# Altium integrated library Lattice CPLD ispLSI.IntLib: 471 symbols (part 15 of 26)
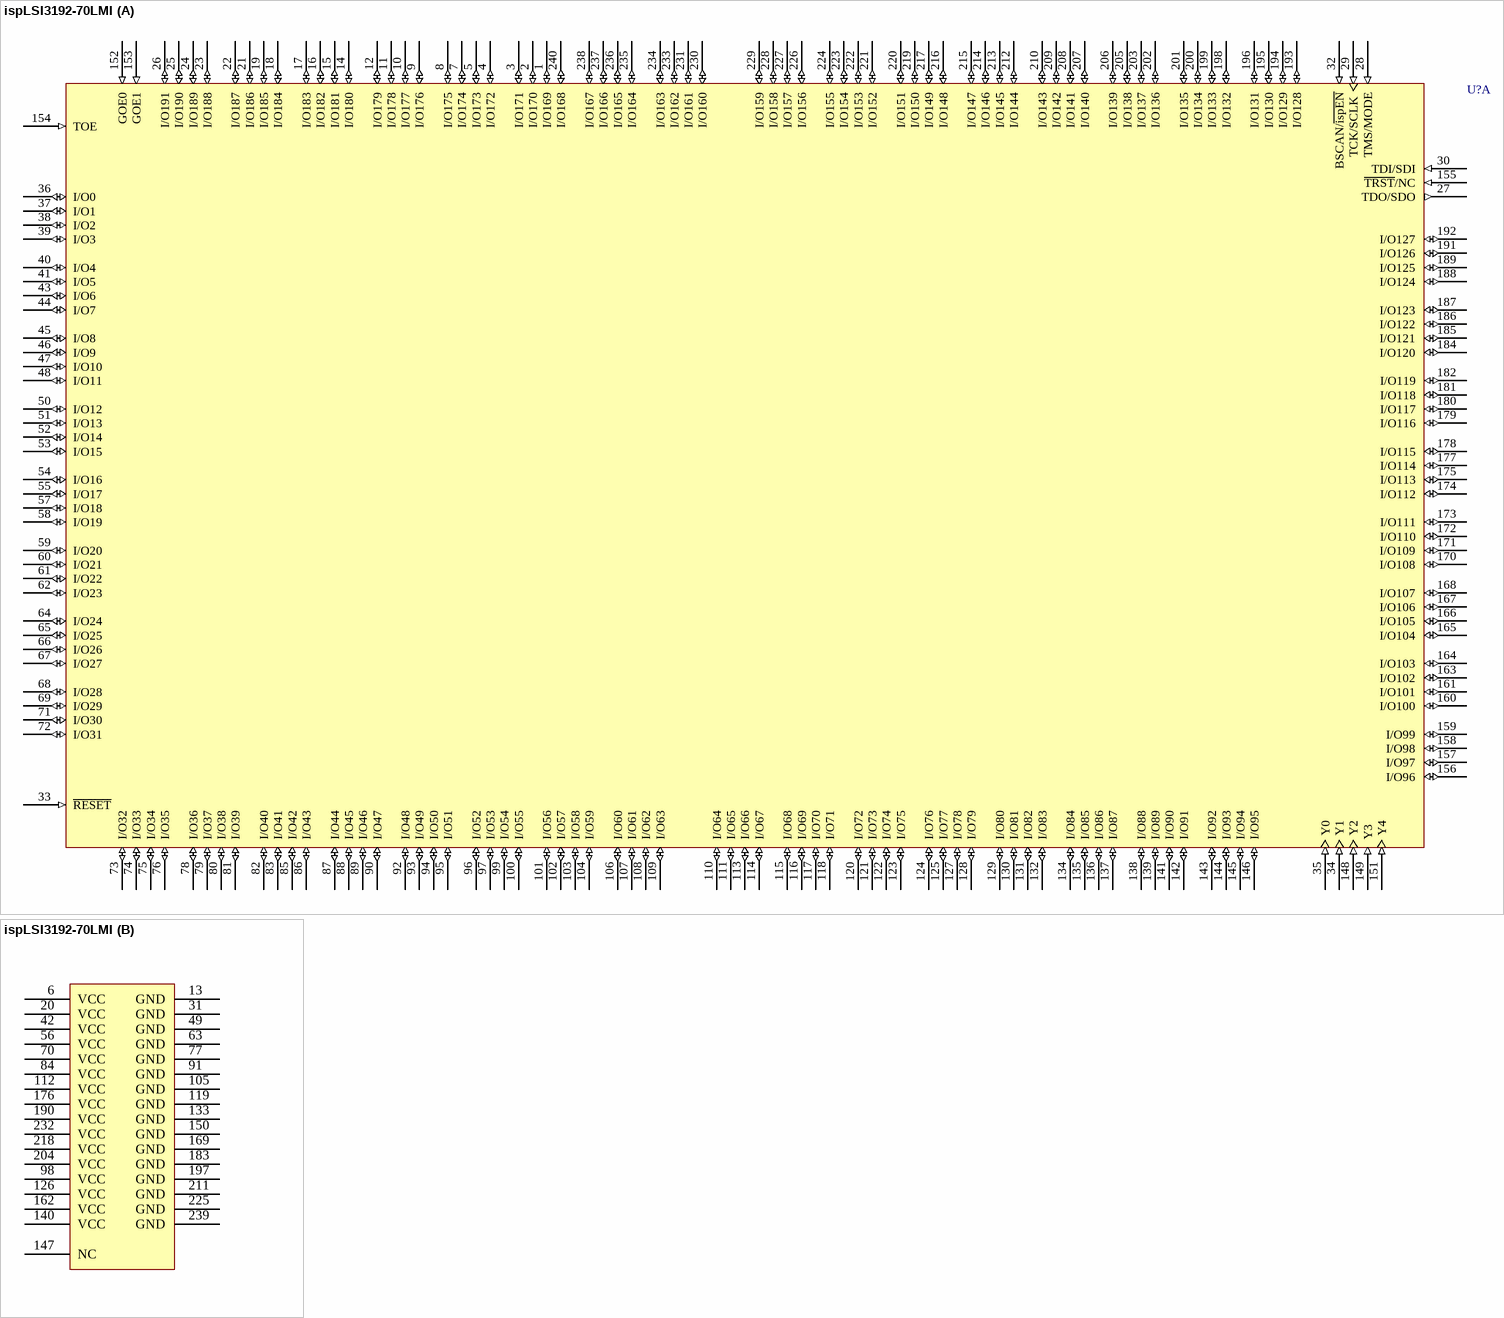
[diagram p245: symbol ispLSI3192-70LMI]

## ispLSI3192-70LMI
designator U?
High-Density Programmable Logic; Note: Pins 27, 28, 29, 30, 32 and 155 have dual function capability.
footprint MQFP240_N (Shrink QFP, 240-Leads, Body 31.7x31.7mm, Pitch 0.5mm, IPC Medium Density)
footprint MQFP240_L (Shrink QFP, 240-Leads, Body 31.7x31.7mm, Pitch 0.5mm, IPC High Density)
footprint MQFP240_M (Shrink QFP, 240-Leads, Body 31.7x31.7mm, Pitch 0.5mm, IPC Low Density)
3D model 3192-MQFP240 (240-Pin Shrink Quad Flat Pack 0.5 mm Pitch)
part A pins: 1 I/O169 (io), 2 I/O170 (io), 3 I/O171 (io), 4 I/O172 (io), 5 I/O173 (io), 7 I/O174 (io), 8 I/O175 (io), 9 I/O176 (io), 10 I/O177 (io), 11 I/O178 (io), 12 I/O179 (io), 14 I/O180 (io), 15 I/O181 (io), 16 I/O182 (io), 17 I/O183 (io), 18 I/O184 (io), 19 I/O185 (io), 21 I/O186 (io), 22 I/O187 (io), 23 I/O188 (io), 24 I/O189 (io), 25 I/O190 (io), 26 I/O191 (io), 27 TDO/SDO (out), 28 TMS/MODE (in), 29 TCK/SCLK (in), 30 TDI/SDI (in), 32 BSCAN/~{ispEN} (in), 33 ~{RESET} (in), 34 Y1 (in), 35 Y0 (in), 36 I/O0 (io), 37 I/O1 (io), 38 I/O2 (io), 39 I/O3 (io), 40 I/O4 (io), 41 I/O5 (io), 43 I/O6 (io), 44 I/O7 (io), 45 I/O8 (io), 46 I/O9 (io), 47 I/O10 (io), 48 I/O11 (io), 50 I/O12 (io), 51 I/O13 (io), 52 I/O14 (io), 53 I/O15 (io), 54 I/O16 (io), 55 I/O17 (io), 57 I/O18 (io), 58 I/O19 (io), 59 I/O20 (io), 60 I/O21 (io), 61 I/O22 (io), 62 I/O23 (io), 64 I/O24 (io), 65 I/O25 (io), 66 I/O26 (io), 67 I/O27 (io), 68 I/O28 (io), 69 I/O29 (io), 71 I/O30 (io), 72 I/O31 (io), 73 I/O32 (io), 74 I/O33 (io), 75 I/O34 (io), 76 I/O35 (io), 78 I/O36 (io), 79 I/O37 (io), 80 I/O38 (io), 81 I/O39 (io), 82 I/O40 (io), 83 I/O41 (io), 85 I/O42 (io), 86 I/O43 (io), 87 I/O44 (io), 88 I/O45 (io), 89 I/O46 (io), 90 I/O47 (io), 92 I/O48 (io), 93 I/O49 (io), 94 I/O50 (io), 95 I/O51 (io), 96 I/O52 (io), 97 I/O53 (io), 99 I/O54 (io), 100 I/O55 (io), 101 I/O56 (io), 102 I/O57 (io), 103 I/O58 (io), 104 I/O59 (io), 106 I/O60 (io), 107 I/O61 (io), 108 I/O62 (io), 109 I/O63 (io), 110 I/O64 (io), 111 I/O65 (io), 113 I/O66 (io), 114 I/O67 (io), 115 I/O68 (io), 116 I/O69 (io), 117 I/O70 (io), 118 I/O71 (io), 120 I/O72 (io), 121 I/O73 (io), 122 I/O74 (io), 123 I/O75 (io), 124 I/O76 (io), 125 I/O77 (io), 127 I/O78 (io), 128 I/O79 (io), 129 I/O80 (io), 130 I/O81 (io), 131 I/O82 (io), 132 I/O83 (io), 134 I/O84 (io), 135 I/O85 (io), 136 I/O86 (io), 137 I/O87 (io), 138 I/O88 (io), 139 I/O89 (io), 141 I/O90 (io), 142 I/O91 (io), 143 I/O92 (io), 144 I/O93 (io), 145 I/O94 (io), 146 I/O95 (io), 148 Y2 (in), 149 Y3 (in), 151 Y4 (in), 152 GOE0 (in), 153 GOE1 (in), 154 TOE (in), 155 ~{TRST}/NC (in), 156 I/O96 (io), 157 I/O97 (io), 158 I/O98 (io), 159 I/O99 (io), 160 I/O100 (io), 161 I/O101 (io), 163 I/O102 (io), 164 I/O103 (io), 165 I/O104 (io), 166 I/O105 (io), 167 I/O106 (io), 168 I/O107 (io), 170 I/O108 (io), 171 I/O109 (io), 172 I/O110 (io), 173 I/O111 (io), 174 I/O112 (io), 175 I/O113 (io), 177 I/O114 (io), 178 I/O115 (io), 179 I/O116 (io), 180 I/O117 (io), 181 I/O118 (io), 182 I/O119 (io), 184 I/O120 (io), 185 I/O121 (io), 186 I/O122 (io), 187 I/O123 (io), 188 I/O124 (io), 189 I/O125 (io), 191 I/O126 (io), 192 I/O127 (io), 193 I/O128 (io), 194 I/O129 (io), 195 I/O130 (io), 196 I/O131 (io), 198 I/O132 (io), 199 I/O133 (io), 200 I/O134 (io), 201 I/O135 (io), 202 I/O136 (io), 203 I/O137 (io), 205 I/O138 (io), 206 I/O139 (io), 207 I/O140 (io), 208 I/O141 (io), 209 I/O142 (io), 210 I/O143 (io), 212 I/O144 (io), 213 I/O145 (io), 214 I/O146 (io), 215 I/O147 (io), 216 I/O148 (io), 217 I/O149 (io), 219 I/O150 (io), 220 I/O151 (io), 221 I/O152 (io), 222 I/O153 (io), 223 I/O154 (io), 224 I/O155 (io), 226 I/O156 (io), 227 I/O157 (io), 228 I/O158 (io), 229 I/O159 (io), 230 I/O160 (io), 231 I/O161 (io), 233 I/O162 (io), 234 I/O163 (io), 235 I/O164 (io), 236 I/O165 (io), 237 I/O166 (io), 238 I/O167 (io), 240 I/O168 (io)
part B pins: 6 VCC (power), 13 GND (power), 20 VCC (power), 31 GND (power), 42 VCC (power), 49 GND (power), 56 VCC (power), 63 GND (power), 70 VCC (power), 77 GND (power), 84 VCC (power), 91 GND (power), 98 VCC (power), 105 GND (power), 112 VCC (power), 119 GND (power), 126 VCC (power), 133 GND (power), 140 VCC (power), 147 NC, 150 GND (power), 162 VCC (power), 169 GND (power), 176 VCC (power), 183 GND (power), 190 VCC (power), 197 GND (power), 204 VCC (power), 211 GND (power), 218 VCC (power), 225 GND (power), 232 VCC (power), 239 GND (power)

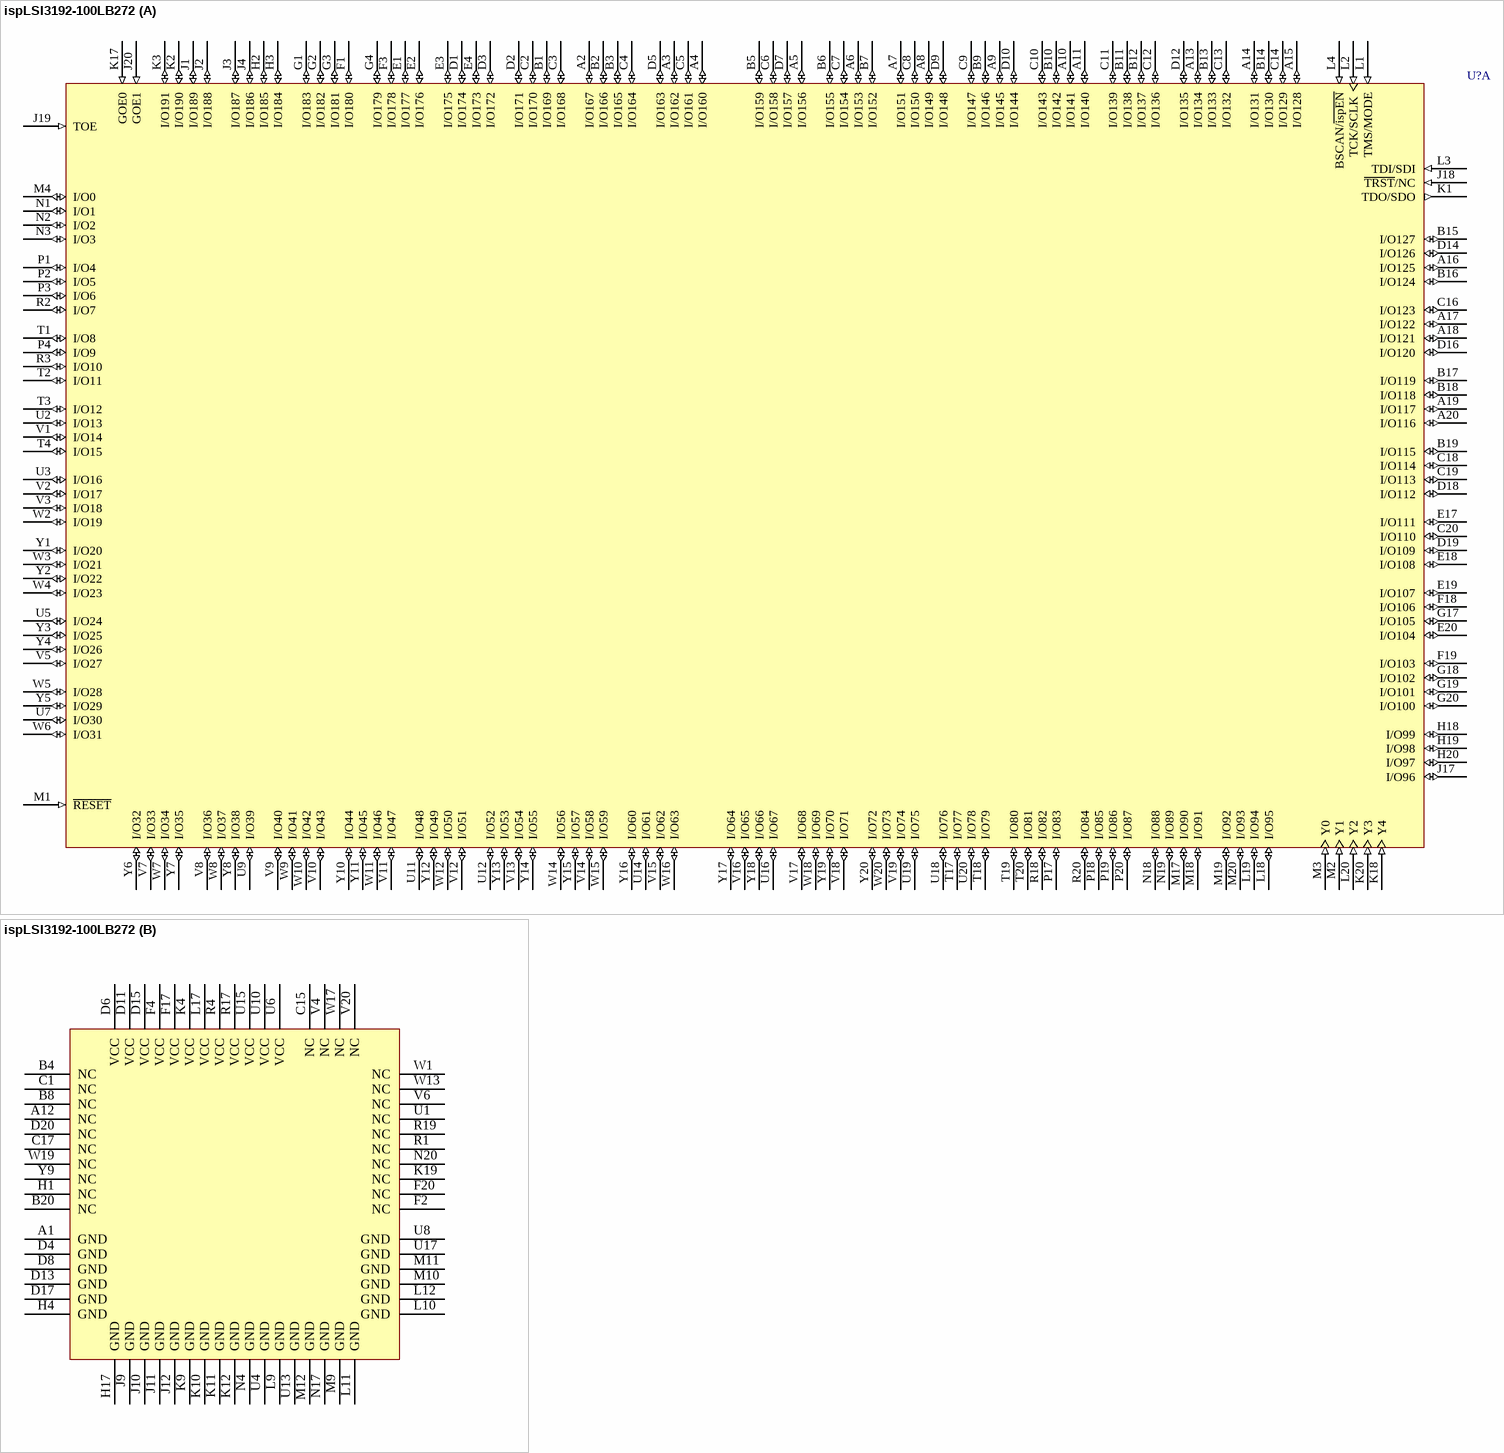
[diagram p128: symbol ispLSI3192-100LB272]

## ispLSI3192-100LB272
designator U?
High-Density Programmable Logic; Note: Pins J18, K1, L1, L2, L3 and L4 have dual function capability.
footprint BGA272 (BGA, 272-Leads, Body 27x27mm, Pitch 1.27mm)
3D model 3192-BGA272 (272-Ball Ball Grid Array (BGA272))
part A pins: A2 I/O167 (io), A3 I/O162 (io), A4 I/O160 (io), A5 I/O156 (io), A6 I/O153 (io), A7 I/O151 (io), A8 I/O149 (io), A9 I/O145 (io), A10 I/O141 (io), A11 I/O140 (io), A13 I/O134 (io), A14 I/O131 (io), A15 I/O128 (io), A16 I/O125 (io), A17 I/O122 (io), A18 I/O121 (io), A19 I/O117 (io), A20 I/O116 (io), B1 I/O169 (io), B2 I/O166 (io), B3 I/O165 (io), B5 I/O159 (io), B6 I/O155 (io), B7 I/O152 (io), B9 I/O146 (io), B10 I/O142 (io), B11 I/O138 (io), B12 I/O137 (io), B13 I/O133 (io), B14 I/O130 (io), B15 I/O127 (io), B16 I/O124 (io), B17 I/O119 (io), B18 I/O118 (io), B19 I/O115 (io), C2 I/O170 (io), C3 I/O168 (io), C4 I/O164 (io), C5 I/O161 (io), C6 I/O158 (io), C7 I/O154 (io), C8 I/O150 (io), C9 I/O147 (io), C10 I/O143 (io), C11 I/O139 (io), C12 I/O136 (io), C13 I/O132 (io), C14 I/O129 (io), C16 I/O123 (io), C18 I/O114 (io), C19 I/O113 (io), C20 I/O110 (io), D1 I/O174 (io), D2 I/O171 (io), D3 I/O172 (io), D5 I/O163 (io), D7 I/O157 (io), D9 I/O148 (io), D10 I/O144 (io), D12 I/O135 (io), D14 I/O126 (io), D16 I/O120 (io), D18 I/O112 (io), D19 I/O109 (io), E1 I/O177 (io), E2 I/O176 (io), E3 I/O175 (io), E4 I/O173 (io), E17 I/O111 (io), E18 I/O108 (io), E19 I/O107 (io), E20 I/O104 (io), F1 I/O180 (io), F3 I/O178 (io), F18 I/O106 (io), F19 I/O103 (io), G1 I/O183 (io), G2 I/O182 (io), G3 I/O181 (io), G4 I/O179 (io), G17 I/O105 (io), G18 I/O102 (io), G19 I/O101 (io), G20 I/O100 (io), H2 I/O185 (io), H3 I/O184 (io), H18 I/O99 (io), H19 I/O98 (io), H20 I/O97 (io), J1 I/O189 (io), J2 I/O188 (io), J3 I/O187 (io), J4 I/O186 (io), J17 I/O96 (io), J18 ~{TRST}/NC (in), J19 TOE (in), J20 GOE1 (in), K1 TDO/SDO (out), K2 I/O190 (io), K3 I/O191 (io), K17 GOE0 (in), K18 Y4 (in), K20 Y3 (in), L1 TMS/MODE (in), L2 TCK/SCLK (in), L3 TDI/SDI (in), L4 BSCAN/~{ispEN} (in), L18 I/O95 (io), L19 I/O94 (io), L20 Y2 (in), M1 ~{RESET} (in), M2 Y1 (in), M3 Y0 (in), M4 I/O0 (io), M17 I/O90 (io), M18 I/O91 (io), M19 I/O92 (io), M20 I/O93 (io), N1 I/O1 (io), N2 I/O2 (io), N3 I/O3 (io), N18 I/O88 (io), N19 I/O89 (io), P1 I/O4 (io), P2 I/O5 (io), P3 I/O6 (io), P4 I/O9 (io), P17 I/O83 (io), P18 I/O85 (io), P19 I/O86 (io), P20 I/O87 (io), R2 I/O7 (io), R3 I/O10 (io), R18 I/O82 (io), R20 I/O84 (io), T1 I/O8 (io), T2 I/O11 (io), T3 I/O12 (io), T4 I/O15 (io), T17 I/O77 (io), T18 I/O79 (io), T19 I/O80 (io), T20 I/O81 (io), U2 I/O13 (io), U3 I/O16 (io), U5 I/O24 (io), U7 I/O30 (io), U9 I/O39 (io), U11 I/O48 (io), U12 I/O52 (io), U14 I/O61 (io), U16 I/O67 (io), U18 I/O76 (io), U19 I/O75 (io), U20 I/O78 (io), V1 I/O14 (io), V2 I/O17 (io), V3 I/O18 (io), V5 I/O27 (io), V7 I/O33 (io), V8 I/O36 (io), V9 I/O40 (io), V10 I/O43 (io), V11 I/O47 (io), V12 I/O51 (io), V13 I/O54 (io), V14 I/O58 (io), V15 I/O62 (io), V16 I/O65 (io), V17 I/O68 (io), V18 I/O71 (io), V19 I/O74 (io), W2 I/O19 (io), W3 I/O21 (io), W4 I/O23 (io), W5 I/O28 (io), W6 I/O31 (io), W7 I/O34 (io), W8 I/O37 (io), W9 I/O41 (io), W10 I/O42 (io), W11 I/O46 (io), W12 I/O50 (io), W14 I/O56 (io), W15 I/O59 (io), W16 I/O63 (io), W18 I/O69 (io), W20 I/O73 (io), Y1 I/O20 (io), Y2 I/O22 (io), Y3 I/O25 (io), Y4 I/O26 (io), Y5 I/O29 (io), Y6 I/O32 (io), Y7 I/O35 (io), Y8 I/O38 (io), Y10 I/O44 (io), Y11 I/O45 (io), Y12 I/O49 (io), Y13 I/O53 (io), Y14 I/O55 (io), Y15 I/O57 (io), Y16 I/O60 (io), Y17 I/O64 (io), Y18 I/O66 (io), Y19 I/O70 (io), Y20 I/O72 (io)
part B pins: A1 GND (power), A12 NC, B4 NC, B8 NC, B20 NC, C1 NC, C15 NC, C17 NC, D4 GND (power), D6 VCC (power), D8 GND (power), D11 VCC (power), D13 GND (power), D15 VCC (power), D17 GND (power), D20 NC, F2 NC, F4 VCC (power), F17 VCC (power), F20 NC, H1 NC, H4 GND (power), H17 GND (power), J9 GND (power), J10 GND (power), J11 GND (power), J12 GND (power), K4 VCC (power), K9 GND (power), K10 GND (power), K11 GND (power), K12 GND (power), K19 NC, L9 GND (power), L10 GND (power), L11 GND (power), L12 GND (power), L17 VCC (power), M9 GND (power), M10 GND (power), M11 GND (power), M12 GND (power), N4 GND (power), N17 GND (power), N20 NC, R1 NC, R4 VCC (power), R17 VCC (power), R19 NC, U1 NC, U4 GND (power), U6 VCC (power), U8 GND (power), U10 VCC (power), U13 GND (power), U15 VCC (power), U17 GND (power), V4 NC, V6 NC, V20 NC, W1 NC, W13 NC, W17 NC, W19 NC, Y9 NC

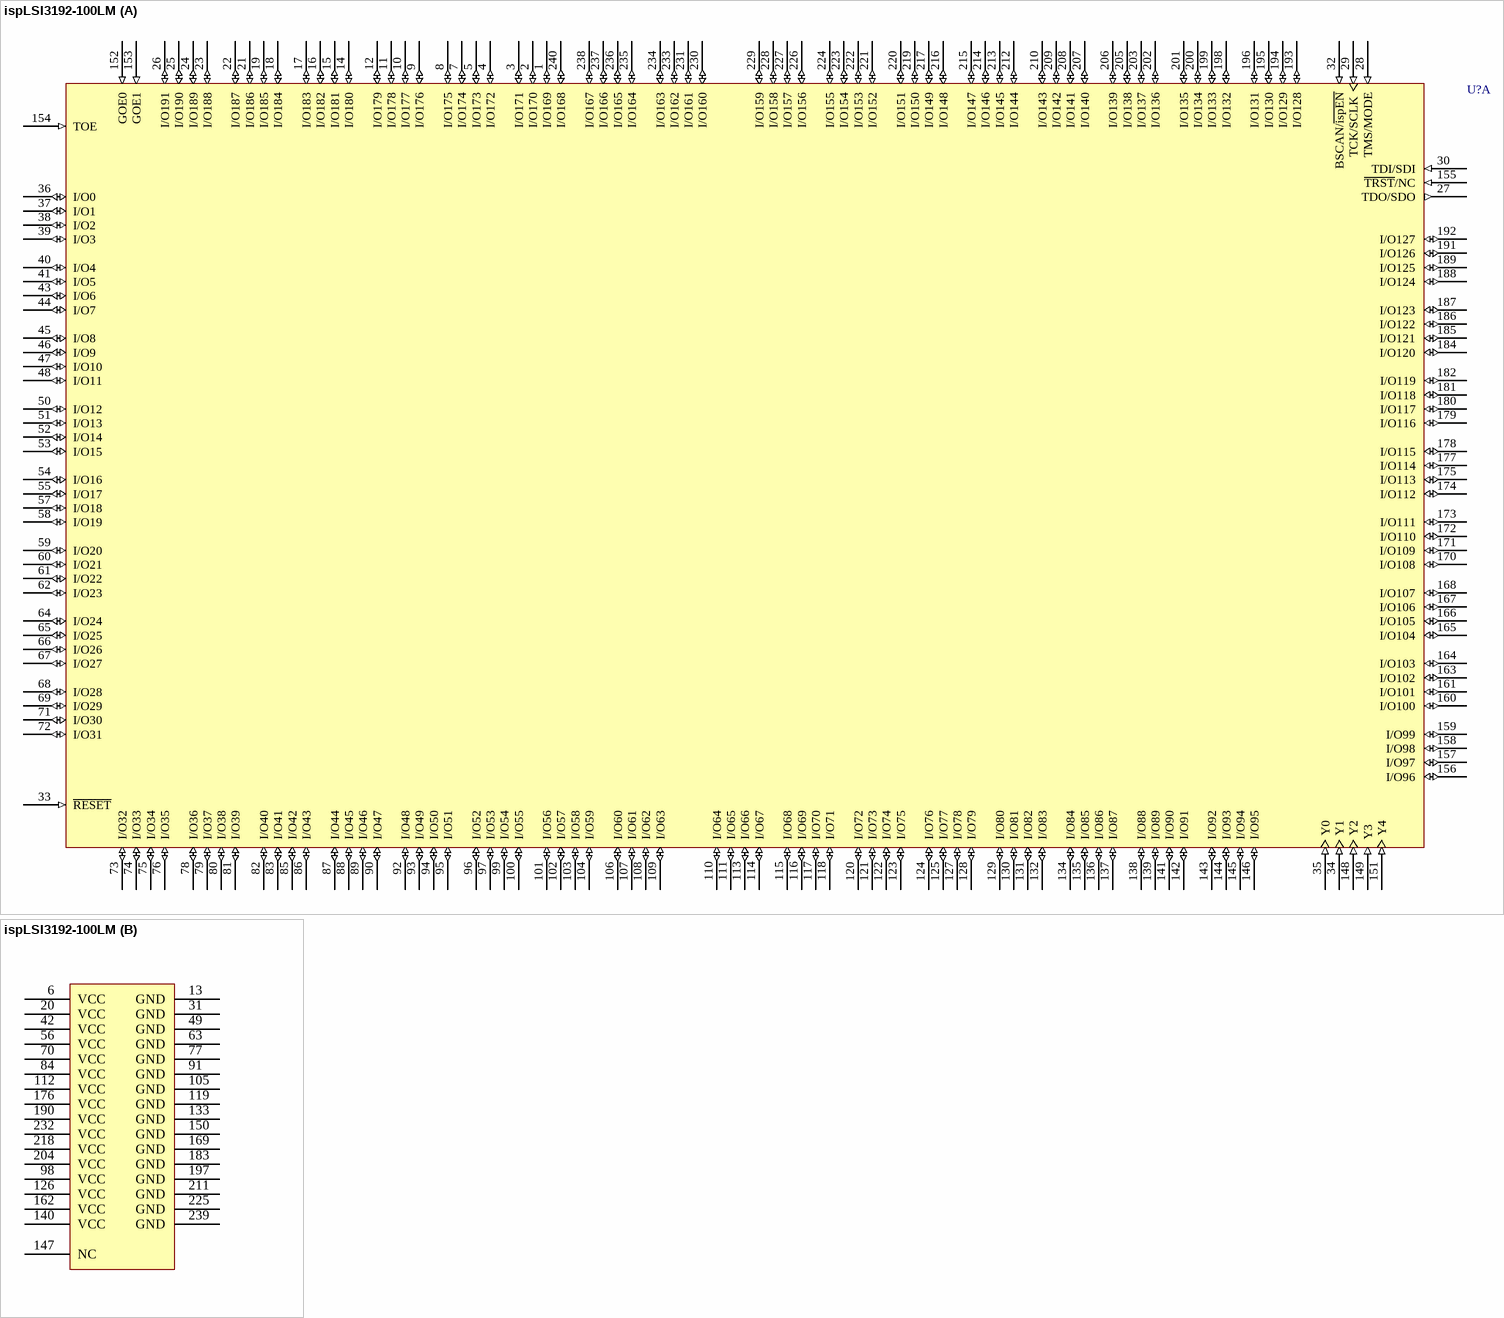
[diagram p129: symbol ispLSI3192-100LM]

## ispLSI3192-100LM
designator U?
High-Density Programmable Logic; Note: Pins 27, 28, 29, 30, 32 and 155 have dual function capability.
footprint MQFP240_N (Shrink QFP, 240-Leads, Body 31.7x31.7mm, Pitch 0.5mm, IPC Medium Density)
footprint MQFP240_L (Shrink QFP, 240-Leads, Body 31.7x31.7mm, Pitch 0.5mm, IPC High Density)
footprint MQFP240_M (Shrink QFP, 240-Leads, Body 31.7x31.7mm, Pitch 0.5mm, IPC Low Density)
3D model 3192-MQFP240 (240-Pin Shrink Quad Flat Pack 0.5 mm Pitch)
part A pins: 1 I/O169 (io), 2 I/O170 (io), 3 I/O171 (io), 4 I/O172 (io), 5 I/O173 (io), 7 I/O174 (io), 8 I/O175 (io), 9 I/O176 (io), 10 I/O177 (io), 11 I/O178 (io), 12 I/O179 (io), 14 I/O180 (io), 15 I/O181 (io), 16 I/O182 (io), 17 I/O183 (io), 18 I/O184 (io), 19 I/O185 (io), 21 I/O186 (io), 22 I/O187 (io), 23 I/O188 (io), 24 I/O189 (io), 25 I/O190 (io), 26 I/O191 (io), 27 TDO/SDO (out), 28 TMS/MODE (in), 29 TCK/SCLK (in), 30 TDI/SDI (in), 32 BSCAN/~{ispEN} (in), 33 ~{RESET} (in), 34 Y1 (in), 35 Y0 (in), 36 I/O0 (io), 37 I/O1 (io), 38 I/O2 (io), 39 I/O3 (io), 40 I/O4 (io), 41 I/O5 (io), 43 I/O6 (io), 44 I/O7 (io), 45 I/O8 (io), 46 I/O9 (io), 47 I/O10 (io), 48 I/O11 (io), 50 I/O12 (io), 51 I/O13 (io), 52 I/O14 (io), 53 I/O15 (io), 54 I/O16 (io), 55 I/O17 (io), 57 I/O18 (io), 58 I/O19 (io), 59 I/O20 (io), 60 I/O21 (io), 61 I/O22 (io), 62 I/O23 (io), 64 I/O24 (io), 65 I/O25 (io), 66 I/O26 (io), 67 I/O27 (io), 68 I/O28 (io), 69 I/O29 (io), 71 I/O30 (io), 72 I/O31 (io), 73 I/O32 (io), 74 I/O33 (io), 75 I/O34 (io), 76 I/O35 (io), 78 I/O36 (io), 79 I/O37 (io), 80 I/O38 (io), 81 I/O39 (io), 82 I/O40 (io), 83 I/O41 (io), 85 I/O42 (io), 86 I/O43 (io), 87 I/O44 (io), 88 I/O45 (io), 89 I/O46 (io), 90 I/O47 (io), 92 I/O48 (io), 93 I/O49 (io), 94 I/O50 (io), 95 I/O51 (io), 96 I/O52 (io), 97 I/O53 (io), 99 I/O54 (io), 100 I/O55 (io), 101 I/O56 (io), 102 I/O57 (io), 103 I/O58 (io), 104 I/O59 (io), 106 I/O60 (io), 107 I/O61 (io), 108 I/O62 (io), 109 I/O63 (io), 110 I/O64 (io), 111 I/O65 (io), 113 I/O66 (io), 114 I/O67 (io), 115 I/O68 (io), 116 I/O69 (io), 117 I/O70 (io), 118 I/O71 (io), 120 I/O72 (io), 121 I/O73 (io), 122 I/O74 (io), 123 I/O75 (io), 124 I/O76 (io), 125 I/O77 (io), 127 I/O78 (io), 128 I/O79 (io), 129 I/O80 (io), 130 I/O81 (io), 131 I/O82 (io), 132 I/O83 (io), 134 I/O84 (io), 135 I/O85 (io), 136 I/O86 (io), 137 I/O87 (io), 138 I/O88 (io), 139 I/O89 (io), 141 I/O90 (io), 142 I/O91 (io), 143 I/O92 (io), 144 I/O93 (io), 145 I/O94 (io), 146 I/O95 (io), 148 Y2 (in), 149 Y3 (in), 151 Y4 (in), 152 GOE0 (in), 153 GOE1 (in), 154 TOE (in), 155 ~{TRST}/NC (in), 156 I/O96 (io), 157 I/O97 (io), 158 I/O98 (io), 159 I/O99 (io), 160 I/O100 (io), 161 I/O101 (io), 163 I/O102 (io), 164 I/O103 (io), 165 I/O104 (io), 166 I/O105 (io), 167 I/O106 (io), 168 I/O107 (io), 170 I/O108 (io), 171 I/O109 (io), 172 I/O110 (io), 173 I/O111 (io), 174 I/O112 (io), 175 I/O113 (io), 177 I/O114 (io), 178 I/O115 (io), 179 I/O116 (io), 180 I/O117 (io), 181 I/O118 (io), 182 I/O119 (io), 184 I/O120 (io), 185 I/O121 (io), 186 I/O122 (io), 187 I/O123 (io), 188 I/O124 (io), 189 I/O125 (io), 191 I/O126 (io), 192 I/O127 (io), 193 I/O128 (io), 194 I/O129 (io), 195 I/O130 (io), 196 I/O131 (io), 198 I/O132 (io), 199 I/O133 (io), 200 I/O134 (io), 201 I/O135 (io), 202 I/O136 (io), 203 I/O137 (io), 205 I/O138 (io), 206 I/O139 (io), 207 I/O140 (io), 208 I/O141 (io), 209 I/O142 (io), 210 I/O143 (io), 212 I/O144 (io), 213 I/O145 (io), 214 I/O146 (io), 215 I/O147 (io), 216 I/O148 (io), 217 I/O149 (io), 219 I/O150 (io), 220 I/O151 (io), 221 I/O152 (io), 222 I/O153 (io), 223 I/O154 (io), 224 I/O155 (io), 226 I/O156 (io), 227 I/O157 (io), 228 I/O158 (io), 229 I/O159 (io), 230 I/O160 (io), 231 I/O161 (io), 233 I/O162 (io), 234 I/O163 (io), 235 I/O164 (io), 236 I/O165 (io), 237 I/O166 (io), 238 I/O167 (io), 240 I/O168 (io)
part B pins: 6 VCC (power), 13 GND (power), 20 VCC (power), 31 GND (power), 42 VCC (power), 49 GND (power), 56 VCC (power), 63 GND (power), 70 VCC (power), 77 GND (power), 84 VCC (power), 91 GND (power), 98 VCC (power), 105 GND (power), 112 VCC (power), 119 GND (power), 126 VCC (power), 133 GND (power), 140 VCC (power), 147 NC, 150 GND (power), 162 VCC (power), 169 GND (power), 176 VCC (power), 183 GND (power), 190 VCC (power), 197 GND (power), 204 VCC (power), 211 GND (power), 218 VCC (power), 225 GND (power), 232 VCC (power), 239 GND (power)

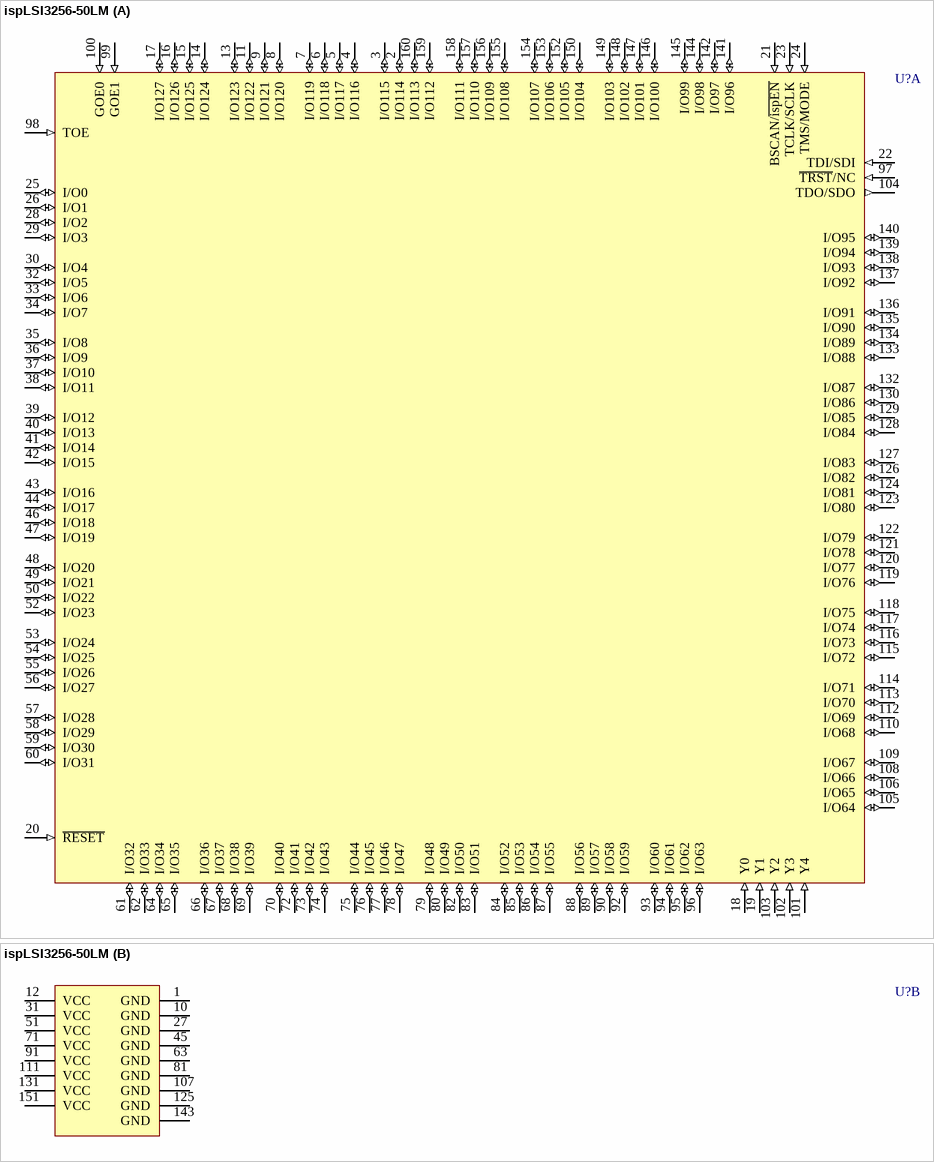
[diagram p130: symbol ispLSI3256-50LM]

## ispLSI3256-50LM
designator U?
High-Density Programmable Logic; Note: Pins 21, 22, 23, 24, 97 and 104 have dual function capability.
footprint MQFP160_N (QFP, 160-Leads, Body 27.7 x 27.7mm, Pitch 0.65mm, IPC Medium Density)
footprint MQFP160_L (QFP, 160-Leads, Body 27.7 x 27.7mm, Pitch 0.65mm, IPC High Density)
footprint MQFP160_M (QFP, 160-Leads, Body 27.7 x 27.7mm, Pitch 0.65mm, IPC Low Density)
3D model 3256-MQFP160 (160-Pin Quad Flat Pack 0.65 mm Pitch)
part A pins: 2 I/O114 (io), 3 I/O115 (io), 4 I/O116 (io), 5 I/O117 (io), 6 I/O118 (io), 7 I/O119 (io), 8 I/O120 (io), 9 I/O121 (io), 11 I/O122 (io), 13 I/O123 (io), 14 I/O124 (io), 15 I/O125 (io), 16 I/O126 (io), 17 I/O127 (io), 18 Y0 (in), 19 Y1 (in), 20 ~{RESET} (in), 21 BSCAN/~{ispEN} (in), 22 TDI/SDI (in), 23 TCLK/SCLK (in), 24 TMS/MODE (in), 25 I/O0 (io), 26 I/O1 (io), 28 I/O2 (io), 29 I/O3 (io), 30 I/O4 (io), 32 I/O5 (io), 33 I/O6 (io), 34 I/O7 (io), 35 I/O8 (io), 36 I/O9 (io), 37 I/O10 (io), 38 I/O11 (io), 39 I/O12 (io), 40 I/O13 (io), 41 I/O14 (io), 42 I/O15 (io), 43 I/O16 (io), 44 I/O17 (io), 46 I/O18 (io), 47 I/O19 (io), 48 I/O20 (io), 49 I/O21 (io), 50 I/O22 (io), 52 I/O23 (io), 53 I/O24 (io), 54 I/O25 (io), 55 I/O26 (io), 56 I/O27 (io), 57 I/O28 (io), 58 I/O29 (io), 59 I/O30 (io), 60 I/O31 (io), 61 I/O32 (io), 62 I/O33 (io), 64 I/O34 (io), 65 I/O35 (io), 66 I/O36 (io), 67 I/O37 (io), 68 I/O38 (io), 69 I/O39 (io), 70 I/O40 (io), 72 I/O41 (io), 73 I/O42 (io), 74 I/O43 (io), 75 I/O44 (io), 76 I/O45 (io), 77 I/O46 (io), 78 I/O47 (io), 79 I/O48 (io), 80 I/O49 (io), 82 I/O50 (io), 83 I/O51 (io), 84 I/O52 (io), 85 I/O53 (io), 86 I/O54 (io), 87 I/O55 (io), 88 I/O56 (io), 89 I/O57 (io), 90 I/O58 (io), 92 I/O59 (io), 93 I/O60 (io), 94 I/O61 (io), 95 I/O62 (io), 96 I/O63 (io), 97 ~{TRST}/NC (in), 98 TOE (in), 99 GOE1 (in), 100 GOE0 (in), 101 Y4 (in), 102 Y3 (in), 103 Y2 (in), 104 TDO/SDO (out), 105 I/O64 (io), 106 I/O65 (io), 108 I/O66 (io), 109 I/O67 (io), 110 I/O68 (io), 112 I/O69 (io), 113 I/O70 (io), 114 I/O71 (io), 115 I/O72 (io), 116 I/O73 (io), 117 I/O74 (io), 118 I/O75 (io), 119 I/O76 (io), 120 I/O77 (io), 121 I/O78 (io), 122 I/O79 (io), 123 I/O80 (io), 124 I/O81 (io), 126 I/O82 (io), 127 I/O83 (io), 128 I/O84 (io), 129 I/O85 (io), 130 I/O86 (io), 132 I/O87 (io), 133 I/O88 (io), 134 I/O89 (io), 135 I/O90 (io), 136 I/O91 (io), 137 I/O92 (io), 138 I/O93 (io), 139 I/O94 (io), 140 I/O95 (io), 141 I/O96 (io), 142 I/O97 (io), 144 I/O98 (io), 145 I/O99 (io), 146 I/O100 (io), 147 I/O101 (io), 148 I/O102 (io), 149 I/O103 (io), 150 I/O104 (io), 152 I/O105 (io), 153 I/O106 (io), 154 I/O107 (io), 155 I/O108 (io), 156 I/O109 (io), 157 I/O110 (io), 158 I/O111 (io), 159 I/O112 (io), 160 I/O113 (io)
part B pins: 1 GND (power), 10 GND (power), 12 VCC (power), 27 GND (power), 31 VCC (power), 45 GND (power), 51 VCC (power), 63 GND (power), 71 VCC (power), 81 GND (power), 91 VCC (power), 107 GND (power), 111 VCC (power), 125 GND (power), 131 VCC (power), 143 GND (power), 151 VCC (power)

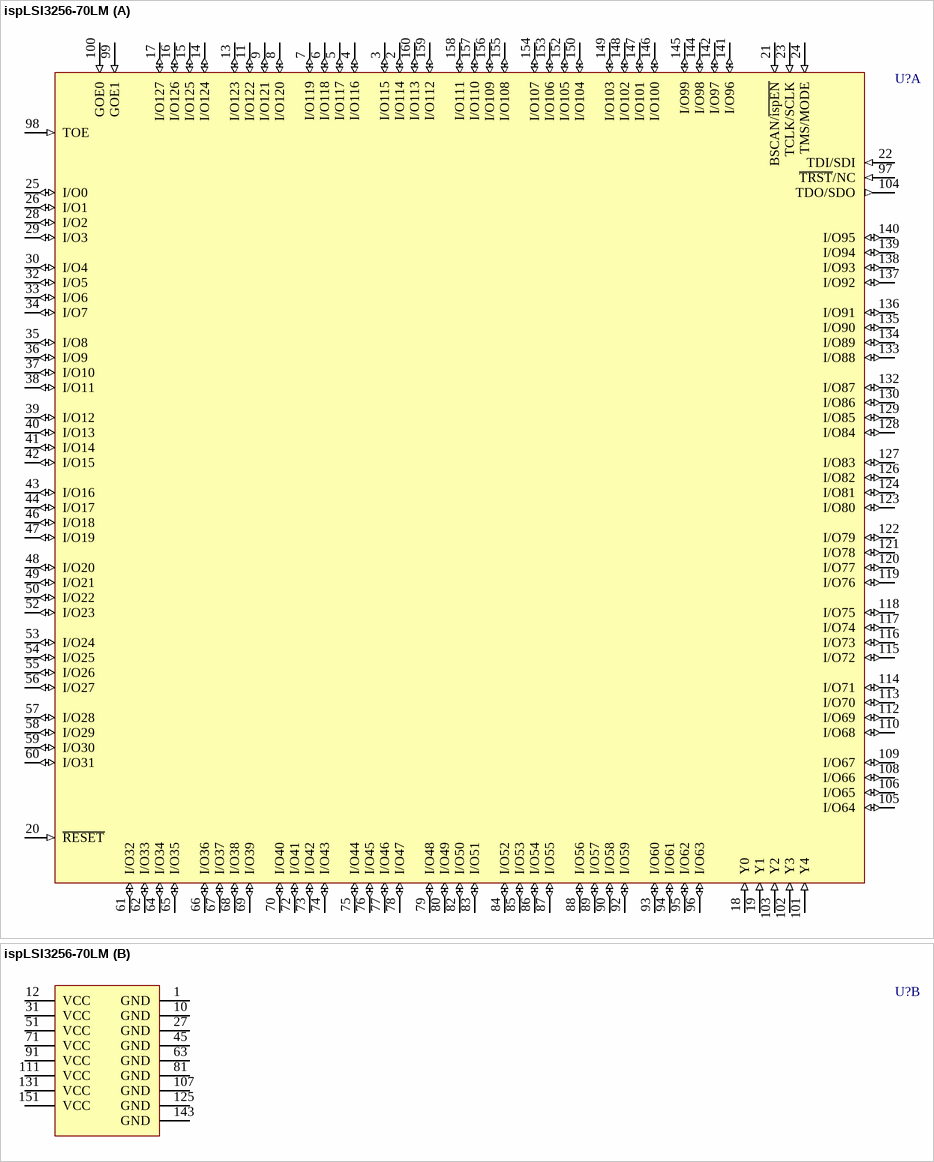
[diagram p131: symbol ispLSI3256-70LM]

## ispLSI3256-70LM
designator U?
High-Density Programmable Logic; Note: Pins 21, 22, 23, 24, 97 and 104 have dual function capability.
footprint MQFP160_N (QFP, 160-Leads, Body 27.7 x 27.7mm, Pitch 0.65mm, IPC Medium Density)
footprint MQFP160_L (QFP, 160-Leads, Body 27.7 x 27.7mm, Pitch 0.65mm, IPC High Density)
footprint MQFP160_M (QFP, 160-Leads, Body 27.7 x 27.7mm, Pitch 0.65mm, IPC Low Density)
3D model 3256-MQFP160 (160-Pin Quad Flat Pack 0.65 mm Pitch)
part A pins: 2 I/O114 (io), 3 I/O115 (io), 4 I/O116 (io), 5 I/O117 (io), 6 I/O118 (io), 7 I/O119 (io), 8 I/O120 (io), 9 I/O121 (io), 11 I/O122 (io), 13 I/O123 (io), 14 I/O124 (io), 15 I/O125 (io), 16 I/O126 (io), 17 I/O127 (io), 18 Y0 (in), 19 Y1 (in), 20 ~{RESET} (in), 21 BSCAN/~{ispEN} (in), 22 TDI/SDI (in), 23 TCLK/SCLK (in), 24 TMS/MODE (in), 25 I/O0 (io), 26 I/O1 (io), 28 I/O2 (io), 29 I/O3 (io), 30 I/O4 (io), 32 I/O5 (io), 33 I/O6 (io), 34 I/O7 (io), 35 I/O8 (io), 36 I/O9 (io), 37 I/O10 (io), 38 I/O11 (io), 39 I/O12 (io), 40 I/O13 (io), 41 I/O14 (io), 42 I/O15 (io), 43 I/O16 (io), 44 I/O17 (io), 46 I/O18 (io), 47 I/O19 (io), 48 I/O20 (io), 49 I/O21 (io), 50 I/O22 (io), 52 I/O23 (io), 53 I/O24 (io), 54 I/O25 (io), 55 I/O26 (io), 56 I/O27 (io), 57 I/O28 (io), 58 I/O29 (io), 59 I/O30 (io), 60 I/O31 (io), 61 I/O32 (io), 62 I/O33 (io), 64 I/O34 (io), 65 I/O35 (io), 66 I/O36 (io), 67 I/O37 (io), 68 I/O38 (io), 69 I/O39 (io), 70 I/O40 (io), 72 I/O41 (io), 73 I/O42 (io), 74 I/O43 (io), 75 I/O44 (io), 76 I/O45 (io), 77 I/O46 (io), 78 I/O47 (io), 79 I/O48 (io), 80 I/O49 (io), 82 I/O50 (io), 83 I/O51 (io), 84 I/O52 (io), 85 I/O53 (io), 86 I/O54 (io), 87 I/O55 (io), 88 I/O56 (io), 89 I/O57 (io), 90 I/O58 (io), 92 I/O59 (io), 93 I/O60 (io), 94 I/O61 (io), 95 I/O62 (io), 96 I/O63 (io), 97 ~{TRST}/NC (in), 98 TOE (in), 99 GOE1 (in), 100 GOE0 (in), 101 Y4 (in), 102 Y3 (in), 103 Y2 (in), 104 TDO/SDO (out), 105 I/O64 (io), 106 I/O65 (io), 108 I/O66 (io), 109 I/O67 (io), 110 I/O68 (io), 112 I/O69 (io), 113 I/O70 (io), 114 I/O71 (io), 115 I/O72 (io), 116 I/O73 (io), 117 I/O74 (io), 118 I/O75 (io), 119 I/O76 (io), 120 I/O77 (io), 121 I/O78 (io), 122 I/O79 (io), 123 I/O80 (io), 124 I/O81 (io), 126 I/O82 (io), 127 I/O83 (io), 128 I/O84 (io), 129 I/O85 (io), 130 I/O86 (io), 132 I/O87 (io), 133 I/O88 (io), 134 I/O89 (io), 135 I/O90 (io), 136 I/O91 (io), 137 I/O92 (io), 138 I/O93 (io), 139 I/O94 (io), 140 I/O95 (io), 141 I/O96 (io), 142 I/O97 (io), 144 I/O98 (io), 145 I/O99 (io), 146 I/O100 (io), 147 I/O101 (io), 148 I/O102 (io), 149 I/O103 (io), 150 I/O104 (io), 152 I/O105 (io), 153 I/O106 (io), 154 I/O107 (io), 155 I/O108 (io), 156 I/O109 (io), 157 I/O110 (io), 158 I/O111 (io), 159 I/O112 (io), 160 I/O113 (io)
part B pins: 1 GND (power), 10 GND (power), 12 VCC (power), 27 GND (power), 31 VCC (power), 45 GND (power), 51 VCC (power), 63 GND (power), 71 VCC (power), 81 GND (power), 91 VCC (power), 107 GND (power), 111 VCC (power), 125 GND (power), 131 VCC (power), 143 GND (power), 151 VCC (power)

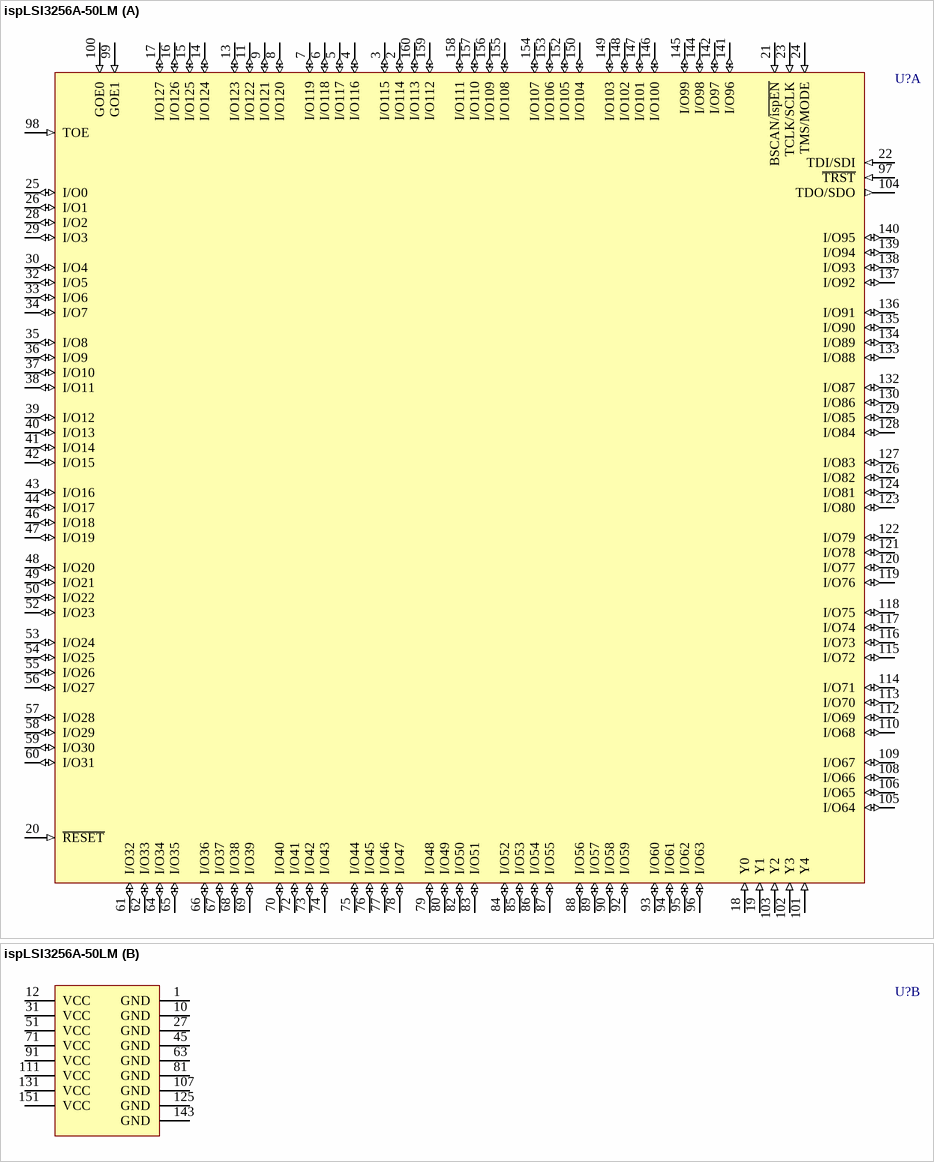
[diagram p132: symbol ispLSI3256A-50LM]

## ispLSI3256A-50LM
designator U?
In-System Programmable High-Density PLD; Note: Pins 21, 22, 23, 24 and 104 have dual function capability.
footprint MQFP160_N (QFP, 160-Leads, Body 27.7 x 27.7mm, Pitch 0.65mm, IPC Medium Density)
footprint MQFP160_L (QFP, 160-Leads, Body 27.7 x 27.7mm, Pitch 0.65mm, IPC High Density)
footprint MQFP160_M (QFP, 160-Leads, Body 27.7 x 27.7mm, Pitch 0.65mm, IPC Low Density)
3D model 3256A-MQFP160 (160-Pin Quad Flat Pack 0.65 mm Pitch)
part A pins: 2 I/O114 (io), 3 I/O115 (io), 4 I/O116 (io), 5 I/O117 (io), 6 I/O118 (io), 7 I/O119 (io), 8 I/O120 (io), 9 I/O121 (io), 11 I/O122 (io), 13 I/O123 (io), 14 I/O124 (io), 15 I/O125 (io), 16 I/O126 (io), 17 I/O127 (io), 18 Y0 (in), 19 Y1 (in), 20 ~{RESET} (in), 21 BSCAN/~{ispEN} (in), 22 TDI/SDI (in), 23 TCLK/SCLK (in), 24 TMS/MODE (in), 25 I/O0 (io), 26 I/O1 (io), 28 I/O2 (io), 29 I/O3 (io), 30 I/O4 (io), 32 I/O5 (io), 33 I/O6 (io), 34 I/O7 (io), 35 I/O8 (io), 36 I/O9 (io), 37 I/O10 (io), 38 I/O11 (io), 39 I/O12 (io), 40 I/O13 (io), 41 I/O14 (io), 42 I/O15 (io), 43 I/O16 (io), 44 I/O17 (io), 46 I/O18 (io), 47 I/O19 (io), 48 I/O20 (io), 49 I/O21 (io), 50 I/O22 (io), 52 I/O23 (io), 53 I/O24 (io), 54 I/O25 (io), 55 I/O26 (io), 56 I/O27 (io), 57 I/O28 (io), 58 I/O29 (io), 59 I/O30 (io), 60 I/O31 (io), 61 I/O32 (io), 62 I/O33 (io), 64 I/O34 (io), 65 I/O35 (io), 66 I/O36 (io), 67 I/O37 (io), 68 I/O38 (io), 69 I/O39 (io), 70 I/O40 (io), 72 I/O41 (io), 73 I/O42 (io), 74 I/O43 (io), 75 I/O44 (io), 76 I/O45 (io), 77 I/O46 (io), 78 I/O47 (io), 79 I/O48 (io), 80 I/O49 (io), 82 I/O50 (io), 83 I/O51 (io), 84 I/O52 (io), 85 I/O53 (io), 86 I/O54 (io), 87 I/O55 (io), 88 I/O56 (io), 89 I/O57 (io), 90 I/O58 (io), 92 I/O59 (io), 93 I/O60 (io), 94 I/O61 (io), 95 I/O62 (io), 96 I/O63 (io), 97 ~{TRST} (in), 98 TOE (in), 99 GOE1 (in), 100 GOE0 (in), 101 Y4 (in), 102 Y3 (in), 103 Y2 (in), 104 TDO/SDO (out), 105 I/O64 (io), 106 I/O65 (io), 108 I/O66 (io), 109 I/O67 (io), 110 I/O68 (io), 112 I/O69 (io), 113 I/O70 (io), 114 I/O71 (io), 115 I/O72 (io), 116 I/O73 (io), 117 I/O74 (io), 118 I/O75 (io), 119 I/O76 (io), 120 I/O77 (io), 121 I/O78 (io), 122 I/O79 (io), 123 I/O80 (io), 124 I/O81 (io), 126 I/O82 (io), 127 I/O83 (io), 128 I/O84 (io), 129 I/O85 (io), 130 I/O86 (io), 132 I/O87 (io), 133 I/O88 (io), 134 I/O89 (io), 135 I/O90 (io), 136 I/O91 (io), 137 I/O92 (io), 138 I/O93 (io), 139 I/O94 (io), 140 I/O95 (io), 141 I/O96 (io), 142 I/O97 (io), 144 I/O98 (io), 145 I/O99 (io), 146 I/O100 (io), 147 I/O101 (io), 148 I/O102 (io), 149 I/O103 (io), 150 I/O104 (io), 152 I/O105 (io), 153 I/O106 (io), 154 I/O107 (io), 155 I/O108 (io), 156 I/O109 (io), 157 I/O110 (io), 158 I/O111 (io), 159 I/O112 (io), 160 I/O113 (io)
part B pins: 1 GND (power), 10 GND (power), 12 VCC (power), 27 GND (power), 31 VCC (power), 45 GND (power), 51 VCC (power), 63 GND (power), 71 VCC (power), 81 GND (power), 91 VCC (power), 107 GND (power), 111 VCC (power), 125 GND (power), 131 VCC (power), 143 GND (power), 151 VCC (power)

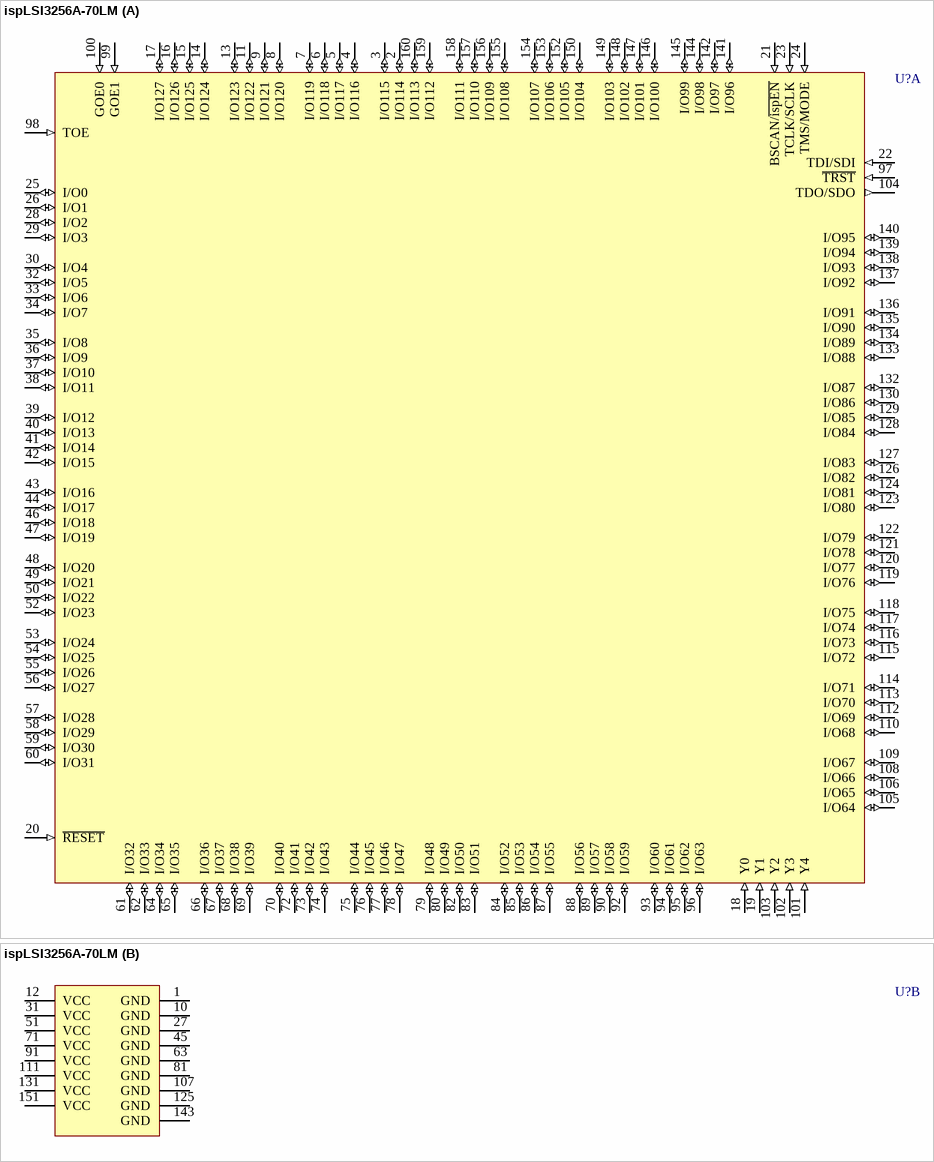
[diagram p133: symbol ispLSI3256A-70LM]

## ispLSI3256A-70LM
designator U?
In-System Programmable High-Density PLD; Note: Pins 21, 22, 23, 24 and 104 have dual function capability.
footprint MQFP160_N (QFP, 160-Leads, Body 27.7 x 27.7mm, Pitch 0.65mm, IPC Medium Density)
footprint MQFP160_L (QFP, 160-Leads, Body 27.7 x 27.7mm, Pitch 0.65mm, IPC High Density)
footprint MQFP160_M (QFP, 160-Leads, Body 27.7 x 27.7mm, Pitch 0.65mm, IPC Low Density)
3D model 3256A-MQFP160 (160-Pin Quad Flat Pack 0.65 mm Pitch)
part A pins: 2 I/O114 (io), 3 I/O115 (io), 4 I/O116 (io), 5 I/O117 (io), 6 I/O118 (io), 7 I/O119 (io), 8 I/O120 (io), 9 I/O121 (io), 11 I/O122 (io), 13 I/O123 (io), 14 I/O124 (io), 15 I/O125 (io), 16 I/O126 (io), 17 I/O127 (io), 18 Y0 (in), 19 Y1 (in), 20 ~{RESET} (in), 21 BSCAN/~{ispEN} (in), 22 TDI/SDI (in), 23 TCLK/SCLK (in), 24 TMS/MODE (in), 25 I/O0 (io), 26 I/O1 (io), 28 I/O2 (io), 29 I/O3 (io), 30 I/O4 (io), 32 I/O5 (io), 33 I/O6 (io), 34 I/O7 (io), 35 I/O8 (io), 36 I/O9 (io), 37 I/O10 (io), 38 I/O11 (io), 39 I/O12 (io), 40 I/O13 (io), 41 I/O14 (io), 42 I/O15 (io), 43 I/O16 (io), 44 I/O17 (io), 46 I/O18 (io), 47 I/O19 (io), 48 I/O20 (io), 49 I/O21 (io), 50 I/O22 (io), 52 I/O23 (io), 53 I/O24 (io), 54 I/O25 (io), 55 I/O26 (io), 56 I/O27 (io), 57 I/O28 (io), 58 I/O29 (io), 59 I/O30 (io), 60 I/O31 (io), 61 I/O32 (io), 62 I/O33 (io), 64 I/O34 (io), 65 I/O35 (io), 66 I/O36 (io), 67 I/O37 (io), 68 I/O38 (io), 69 I/O39 (io), 70 I/O40 (io), 72 I/O41 (io), 73 I/O42 (io), 74 I/O43 (io), 75 I/O44 (io), 76 I/O45 (io), 77 I/O46 (io), 78 I/O47 (io), 79 I/O48 (io), 80 I/O49 (io), 82 I/O50 (io), 83 I/O51 (io), 84 I/O52 (io), 85 I/O53 (io), 86 I/O54 (io), 87 I/O55 (io), 88 I/O56 (io), 89 I/O57 (io), 90 I/O58 (io), 92 I/O59 (io), 93 I/O60 (io), 94 I/O61 (io), 95 I/O62 (io), 96 I/O63 (io), 97 ~{TRST} (in), 98 TOE (in), 99 GOE1 (in), 100 GOE0 (in), 101 Y4 (in), 102 Y3 (in), 103 Y2 (in), 104 TDO/SDO (out), 105 I/O64 (io), 106 I/O65 (io), 108 I/O66 (io), 109 I/O67 (io), 110 I/O68 (io), 112 I/O69 (io), 113 I/O70 (io), 114 I/O71 (io), 115 I/O72 (io), 116 I/O73 (io), 117 I/O74 (io), 118 I/O75 (io), 119 I/O76 (io), 120 I/O77 (io), 121 I/O78 (io), 122 I/O79 (io), 123 I/O80 (io), 124 I/O81 (io), 126 I/O82 (io), 127 I/O83 (io), 128 I/O84 (io), 129 I/O85 (io), 130 I/O86 (io), 132 I/O87 (io), 133 I/O88 (io), 134 I/O89 (io), 135 I/O90 (io), 136 I/O91 (io), 137 I/O92 (io), 138 I/O93 (io), 139 I/O94 (io), 140 I/O95 (io), 141 I/O96 (io), 142 I/O97 (io), 144 I/O98 (io), 145 I/O99 (io), 146 I/O100 (io), 147 I/O101 (io), 148 I/O102 (io), 149 I/O103 (io), 150 I/O104 (io), 152 I/O105 (io), 153 I/O106 (io), 154 I/O107 (io), 155 I/O108 (io), 156 I/O109 (io), 157 I/O110 (io), 158 I/O111 (io), 159 I/O112 (io), 160 I/O113 (io)
part B pins: 1 GND (power), 10 GND (power), 12 VCC (power), 27 GND (power), 31 VCC (power), 45 GND (power), 51 VCC (power), 63 GND (power), 71 VCC (power), 81 GND (power), 91 VCC (power), 107 GND (power), 111 VCC (power), 125 GND (power), 131 VCC (power), 143 GND (power), 151 VCC (power)

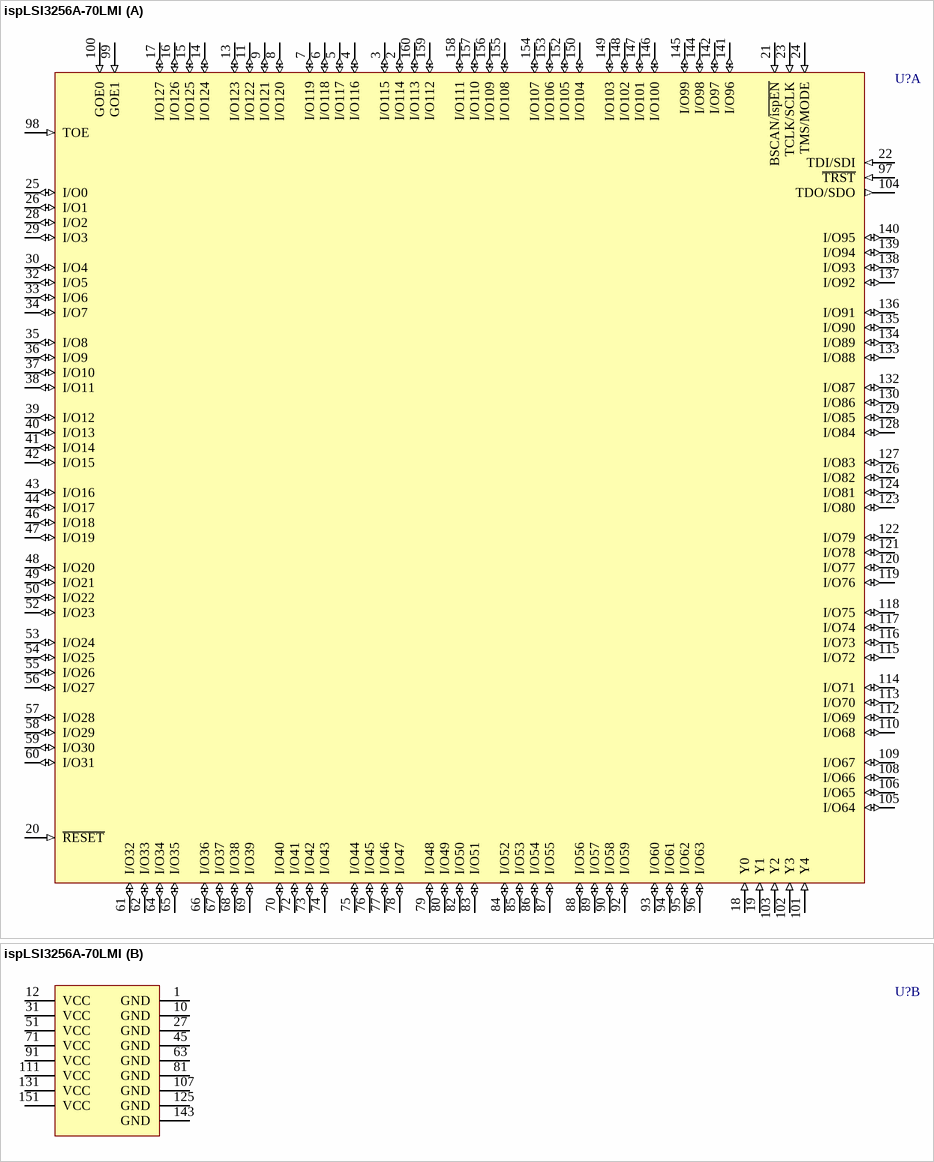
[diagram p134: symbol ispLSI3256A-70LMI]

## ispLSI3256A-70LMI
designator U?
In-System Programmable High-Density PLD; Note: Pins 21, 22, 23, 24 and 104 have dual function capability.
footprint MQFP160_N (QFP, 160-Leads, Body 27.7 x 27.7mm, Pitch 0.65mm, IPC Medium Density)
footprint MQFP160_L (QFP, 160-Leads, Body 27.7 x 27.7mm, Pitch 0.65mm, IPC High Density)
footprint MQFP160_M (QFP, 160-Leads, Body 27.7 x 27.7mm, Pitch 0.65mm, IPC Low Density)
3D model 3256A-MQFP160 (160-Pin Quad Flat Pack 0.65 mm Pitch)
part A pins: 2 I/O114 (io), 3 I/O115 (io), 4 I/O116 (io), 5 I/O117 (io), 6 I/O118 (io), 7 I/O119 (io), 8 I/O120 (io), 9 I/O121 (io), 11 I/O122 (io), 13 I/O123 (io), 14 I/O124 (io), 15 I/O125 (io), 16 I/O126 (io), 17 I/O127 (io), 18 Y0 (in), 19 Y1 (in), 20 ~{RESET} (in), 21 BSCAN/~{ispEN} (in), 22 TDI/SDI (in), 23 TCLK/SCLK (in), 24 TMS/MODE (in), 25 I/O0 (io), 26 I/O1 (io), 28 I/O2 (io), 29 I/O3 (io), 30 I/O4 (io), 32 I/O5 (io), 33 I/O6 (io), 34 I/O7 (io), 35 I/O8 (io), 36 I/O9 (io), 37 I/O10 (io), 38 I/O11 (io), 39 I/O12 (io), 40 I/O13 (io), 41 I/O14 (io), 42 I/O15 (io), 43 I/O16 (io), 44 I/O17 (io), 46 I/O18 (io), 47 I/O19 (io), 48 I/O20 (io), 49 I/O21 (io), 50 I/O22 (io), 52 I/O23 (io), 53 I/O24 (io), 54 I/O25 (io), 55 I/O26 (io), 56 I/O27 (io), 57 I/O28 (io), 58 I/O29 (io), 59 I/O30 (io), 60 I/O31 (io), 61 I/O32 (io), 62 I/O33 (io), 64 I/O34 (io), 65 I/O35 (io), 66 I/O36 (io), 67 I/O37 (io), 68 I/O38 (io), 69 I/O39 (io), 70 I/O40 (io), 72 I/O41 (io), 73 I/O42 (io), 74 I/O43 (io), 75 I/O44 (io), 76 I/O45 (io), 77 I/O46 (io), 78 I/O47 (io), 79 I/O48 (io), 80 I/O49 (io), 82 I/O50 (io), 83 I/O51 (io), 84 I/O52 (io), 85 I/O53 (io), 86 I/O54 (io), 87 I/O55 (io), 88 I/O56 (io), 89 I/O57 (io), 90 I/O58 (io), 92 I/O59 (io), 93 I/O60 (io), 94 I/O61 (io), 95 I/O62 (io), 96 I/O63 (io), 97 ~{TRST} (in), 98 TOE (in), 99 GOE1 (in), 100 GOE0 (in), 101 Y4 (in), 102 Y3 (in), 103 Y2 (in), 104 TDO/SDO (out), 105 I/O64 (io), 106 I/O65 (io), 108 I/O66 (io), 109 I/O67 (io), 110 I/O68 (io), 112 I/O69 (io), 113 I/O70 (io), 114 I/O71 (io), 115 I/O72 (io), 116 I/O73 (io), 117 I/O74 (io), 118 I/O75 (io), 119 I/O76 (io), 120 I/O77 (io), 121 I/O78 (io), 122 I/O79 (io), 123 I/O80 (io), 124 I/O81 (io), 126 I/O82 (io), 127 I/O83 (io), 128 I/O84 (io), 129 I/O85 (io), 130 I/O86 (io), 132 I/O87 (io), 133 I/O88 (io), 134 I/O89 (io), 135 I/O90 (io), 136 I/O91 (io), 137 I/O92 (io), 138 I/O93 (io), 139 I/O94 (io), 140 I/O95 (io), 141 I/O96 (io), 142 I/O97 (io), 144 I/O98 (io), 145 I/O99 (io), 146 I/O100 (io), 147 I/O101 (io), 148 I/O102 (io), 149 I/O103 (io), 150 I/O104 (io), 152 I/O105 (io), 153 I/O106 (io), 154 I/O107 (io), 155 I/O108 (io), 156 I/O109 (io), 157 I/O110 (io), 158 I/O111 (io), 159 I/O112 (io), 160 I/O113 (io)
part B pins: 1 GND (power), 10 GND (power), 12 VCC (power), 27 GND (power), 31 VCC (power), 45 GND (power), 51 VCC (power), 63 GND (power), 71 VCC (power), 81 GND (power), 91 VCC (power), 107 GND (power), 111 VCC (power), 125 GND (power), 131 VCC (power), 143 GND (power), 151 VCC (power)

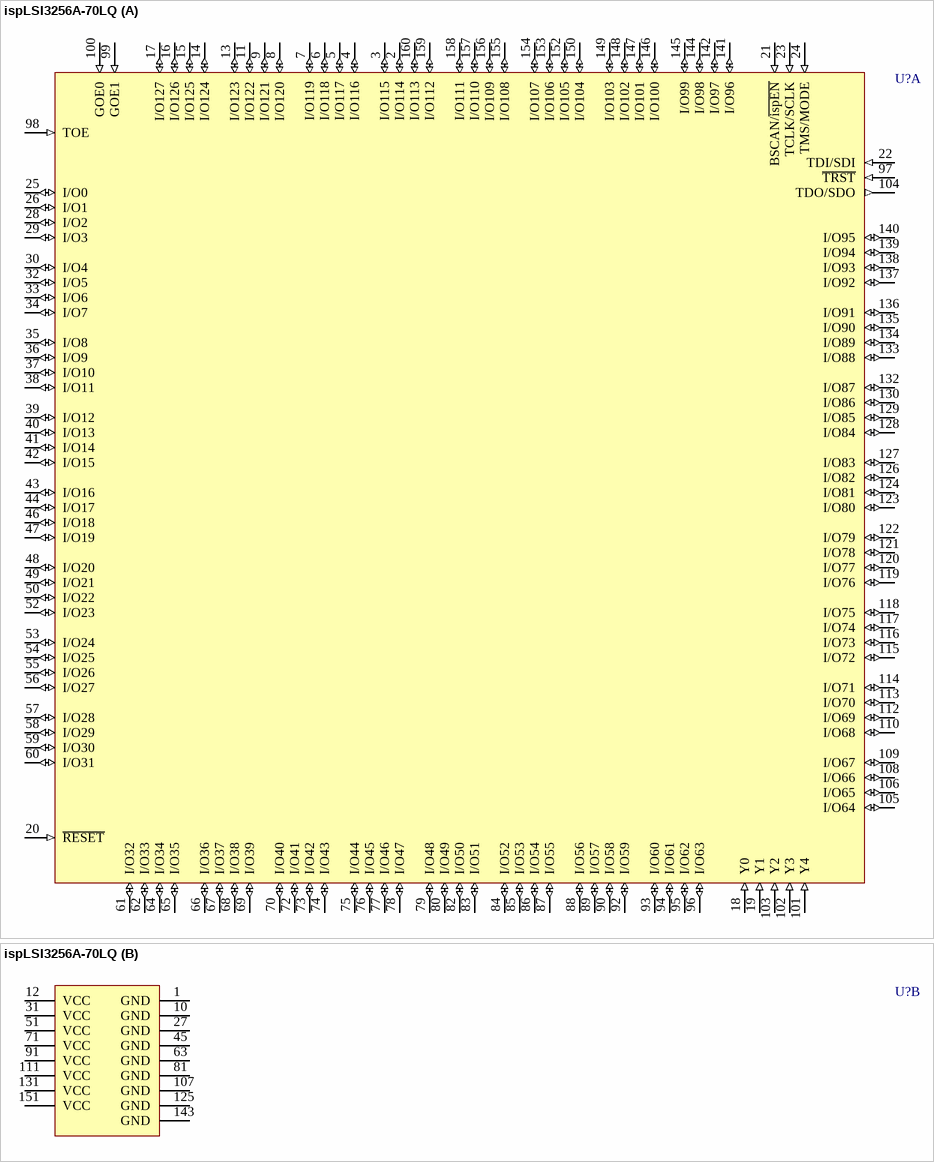
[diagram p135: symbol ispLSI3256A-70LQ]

## ispLSI3256A-70LQ
designator U?
In-System Programmable High-Density PLD; Note: Pins 21, 22, 23, 24 and 104 have dual function capability.
footprint PQFP160_N (QFP, 160-Leads, Body 28 x 28mm, Pitch 0.65mm, IPC Medium Density)
footprint PQFP160_L (QFP, 160-Leads, Body 28 x 28mm, Pitch 0.65mm, IPC High Density)
footprint PQFP160_M (QFP, 160-Leads, Body 28 x 28mm, Pitch 0.65mm, IPC Low Density)
3D model 3256A-PQFP160 (160-Pin Quad Flat Pack 0.65 mm Pitch)
part A pins: 2 I/O114 (io), 3 I/O115 (io), 4 I/O116 (io), 5 I/O117 (io), 6 I/O118 (io), 7 I/O119 (io), 8 I/O120 (io), 9 I/O121 (io), 11 I/O122 (io), 13 I/O123 (io), 14 I/O124 (io), 15 I/O125 (io), 16 I/O126 (io), 17 I/O127 (io), 18 Y0 (in), 19 Y1 (in), 20 ~{RESET} (in), 21 BSCAN/~{ispEN} (in), 22 TDI/SDI (in), 23 TCLK/SCLK (in), 24 TMS/MODE (in), 25 I/O0 (io), 26 I/O1 (io), 28 I/O2 (io), 29 I/O3 (io), 30 I/O4 (io), 32 I/O5 (io), 33 I/O6 (io), 34 I/O7 (io), 35 I/O8 (io), 36 I/O9 (io), 37 I/O10 (io), 38 I/O11 (io), 39 I/O12 (io), 40 I/O13 (io), 41 I/O14 (io), 42 I/O15 (io), 43 I/O16 (io), 44 I/O17 (io), 46 I/O18 (io), 47 I/O19 (io), 48 I/O20 (io), 49 I/O21 (io), 50 I/O22 (io), 52 I/O23 (io), 53 I/O24 (io), 54 I/O25 (io), 55 I/O26 (io), 56 I/O27 (io), 57 I/O28 (io), 58 I/O29 (io), 59 I/O30 (io), 60 I/O31 (io), 61 I/O32 (io), 62 I/O33 (io), 64 I/O34 (io), 65 I/O35 (io), 66 I/O36 (io), 67 I/O37 (io), 68 I/O38 (io), 69 I/O39 (io), 70 I/O40 (io), 72 I/O41 (io), 73 I/O42 (io), 74 I/O43 (io), 75 I/O44 (io), 76 I/O45 (io), 77 I/O46 (io), 78 I/O47 (io), 79 I/O48 (io), 80 I/O49 (io), 82 I/O50 (io), 83 I/O51 (io), 84 I/O52 (io), 85 I/O53 (io), 86 I/O54 (io), 87 I/O55 (io), 88 I/O56 (io), 89 I/O57 (io), 90 I/O58 (io), 92 I/O59 (io), 93 I/O60 (io), 94 I/O61 (io), 95 I/O62 (io), 96 I/O63 (io), 97 ~{TRST} (in), 98 TOE (in), 99 GOE1 (in), 100 GOE0 (in), 101 Y4 (in), 102 Y3 (in), 103 Y2 (in), 104 TDO/SDO (out), 105 I/O64 (io), 106 I/O65 (io), 108 I/O66 (io), 109 I/O67 (io), 110 I/O68 (io), 112 I/O69 (io), 113 I/O70 (io), 114 I/O71 (io), 115 I/O72 (io), 116 I/O73 (io), 117 I/O74 (io), 118 I/O75 (io), 119 I/O76 (io), 120 I/O77 (io), 121 I/O78 (io), 122 I/O79 (io), 123 I/O80 (io), 124 I/O81 (io), 126 I/O82 (io), 127 I/O83 (io), 128 I/O84 (io), 129 I/O85 (io), 130 I/O86 (io), 132 I/O87 (io), 133 I/O88 (io), 134 I/O89 (io), 135 I/O90 (io), 136 I/O91 (io), 137 I/O92 (io), 138 I/O93 (io), 139 I/O94 (io), 140 I/O95 (io), 141 I/O96 (io), 142 I/O97 (io), 144 I/O98 (io), 145 I/O99 (io), 146 I/O100 (io), 147 I/O101 (io), 148 I/O102 (io), 149 I/O103 (io), 150 I/O104 (io), 152 I/O105 (io), 153 I/O106 (io), 154 I/O107 (io), 155 I/O108 (io), 156 I/O109 (io), 157 I/O110 (io), 158 I/O111 (io), 159 I/O112 (io), 160 I/O113 (io)
part B pins: 1 GND (power), 10 GND (power), 12 VCC (power), 27 GND (power), 31 VCC (power), 45 GND (power), 51 VCC (power), 63 GND (power), 71 VCC (power), 81 GND (power), 91 VCC (power), 107 GND (power), 111 VCC (power), 125 GND (power), 131 VCC (power), 143 GND (power), 151 VCC (power)

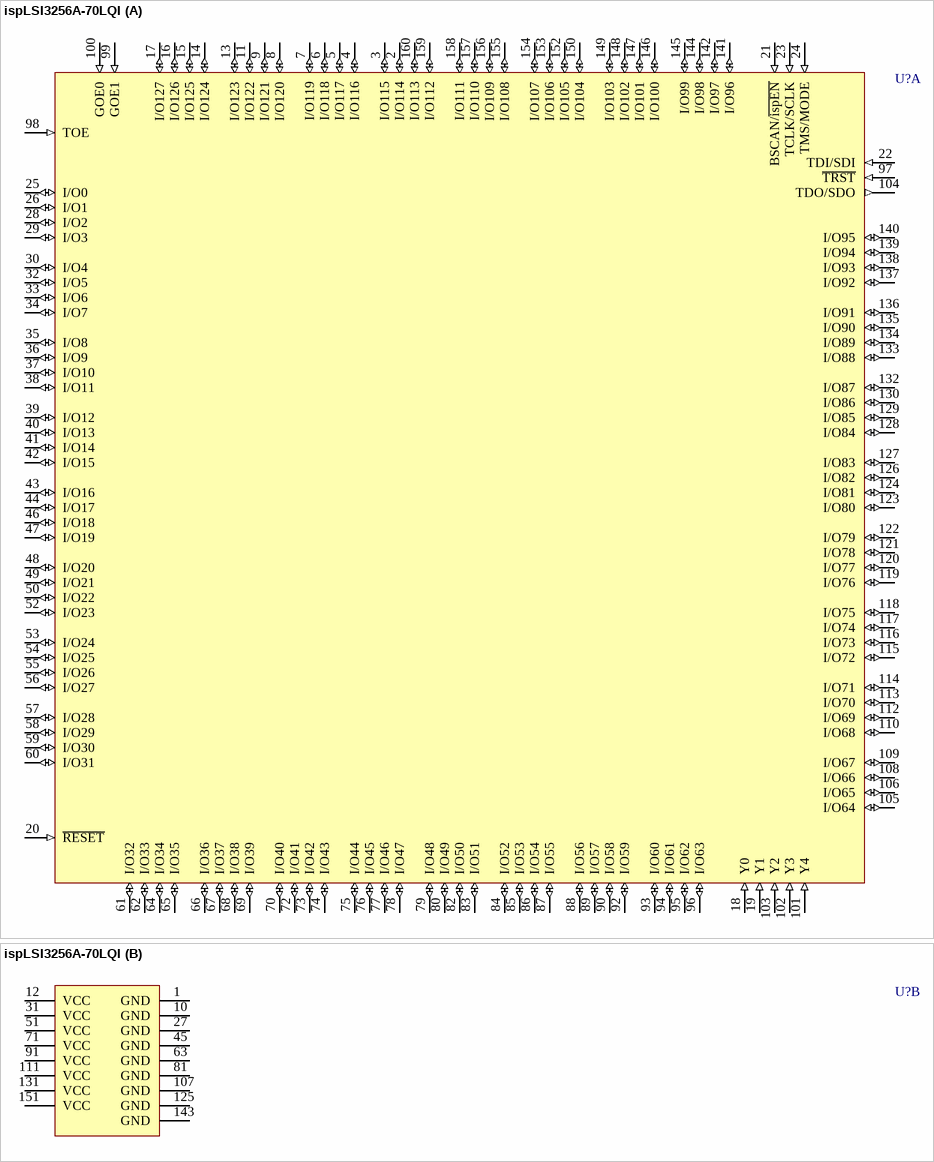
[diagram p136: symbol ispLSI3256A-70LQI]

## ispLSI3256A-70LQI
designator U?
In-System Programmable High-Density PLD; Note: Pins 21, 22, 23, 24 and 104 have dual function capability.
footprint PQFP160_N (QFP, 160-Leads, Body 28 x 28mm, Pitch 0.65mm, IPC Medium Density)
footprint PQFP160_L (QFP, 160-Leads, Body 28 x 28mm, Pitch 0.65mm, IPC High Density)
footprint PQFP160_M (QFP, 160-Leads, Body 28 x 28mm, Pitch 0.65mm, IPC Low Density)
3D model 3256A-PQFP160 (160-Pin Quad Flat Pack 0.65 mm Pitch)
part A pins: 2 I/O114 (io), 3 I/O115 (io), 4 I/O116 (io), 5 I/O117 (io), 6 I/O118 (io), 7 I/O119 (io), 8 I/O120 (io), 9 I/O121 (io), 11 I/O122 (io), 13 I/O123 (io), 14 I/O124 (io), 15 I/O125 (io), 16 I/O126 (io), 17 I/O127 (io), 18 Y0 (in), 19 Y1 (in), 20 ~{RESET} (in), 21 BSCAN/~{ispEN} (in), 22 TDI/SDI (in), 23 TCLK/SCLK (in), 24 TMS/MODE (in), 25 I/O0 (io), 26 I/O1 (io), 28 I/O2 (io), 29 I/O3 (io), 30 I/O4 (io), 32 I/O5 (io), 33 I/O6 (io), 34 I/O7 (io), 35 I/O8 (io), 36 I/O9 (io), 37 I/O10 (io), 38 I/O11 (io), 39 I/O12 (io), 40 I/O13 (io), 41 I/O14 (io), 42 I/O15 (io), 43 I/O16 (io), 44 I/O17 (io), 46 I/O18 (io), 47 I/O19 (io), 48 I/O20 (io), 49 I/O21 (io), 50 I/O22 (io), 52 I/O23 (io), 53 I/O24 (io), 54 I/O25 (io), 55 I/O26 (io), 56 I/O27 (io), 57 I/O28 (io), 58 I/O29 (io), 59 I/O30 (io), 60 I/O31 (io), 61 I/O32 (io), 62 I/O33 (io), 64 I/O34 (io), 65 I/O35 (io), 66 I/O36 (io), 67 I/O37 (io), 68 I/O38 (io), 69 I/O39 (io), 70 I/O40 (io), 72 I/O41 (io), 73 I/O42 (io), 74 I/O43 (io), 75 I/O44 (io), 76 I/O45 (io), 77 I/O46 (io), 78 I/O47 (io), 79 I/O48 (io), 80 I/O49 (io), 82 I/O50 (io), 83 I/O51 (io), 84 I/O52 (io), 85 I/O53 (io), 86 I/O54 (io), 87 I/O55 (io), 88 I/O56 (io), 89 I/O57 (io), 90 I/O58 (io), 92 I/O59 (io), 93 I/O60 (io), 94 I/O61 (io), 95 I/O62 (io), 96 I/O63 (io), 97 ~{TRST} (in), 98 TOE (in), 99 GOE1 (in), 100 GOE0 (in), 101 Y4 (in), 102 Y3 (in), 103 Y2 (in), 104 TDO/SDO (out), 105 I/O64 (io), 106 I/O65 (io), 108 I/O66 (io), 109 I/O67 (io), 110 I/O68 (io), 112 I/O69 (io), 113 I/O70 (io), 114 I/O71 (io), 115 I/O72 (io), 116 I/O73 (io), 117 I/O74 (io), 118 I/O75 (io), 119 I/O76 (io), 120 I/O77 (io), 121 I/O78 (io), 122 I/O79 (io), 123 I/O80 (io), 124 I/O81 (io), 126 I/O82 (io), 127 I/O83 (io), 128 I/O84 (io), 129 I/O85 (io), 130 I/O86 (io), 132 I/O87 (io), 133 I/O88 (io), 134 I/O89 (io), 135 I/O90 (io), 136 I/O91 (io), 137 I/O92 (io), 138 I/O93 (io), 139 I/O94 (io), 140 I/O95 (io), 141 I/O96 (io), 142 I/O97 (io), 144 I/O98 (io), 145 I/O99 (io), 146 I/O100 (io), 147 I/O101 (io), 148 I/O102 (io), 149 I/O103 (io), 150 I/O104 (io), 152 I/O105 (io), 153 I/O106 (io), 154 I/O107 (io), 155 I/O108 (io), 156 I/O109 (io), 157 I/O110 (io), 158 I/O111 (io), 159 I/O112 (io), 160 I/O113 (io)
part B pins: 1 GND (power), 10 GND (power), 12 VCC (power), 27 GND (power), 31 VCC (power), 45 GND (power), 51 VCC (power), 63 GND (power), 71 VCC (power), 81 GND (power), 91 VCC (power), 107 GND (power), 111 VCC (power), 125 GND (power), 131 VCC (power), 143 GND (power), 151 VCC (power)

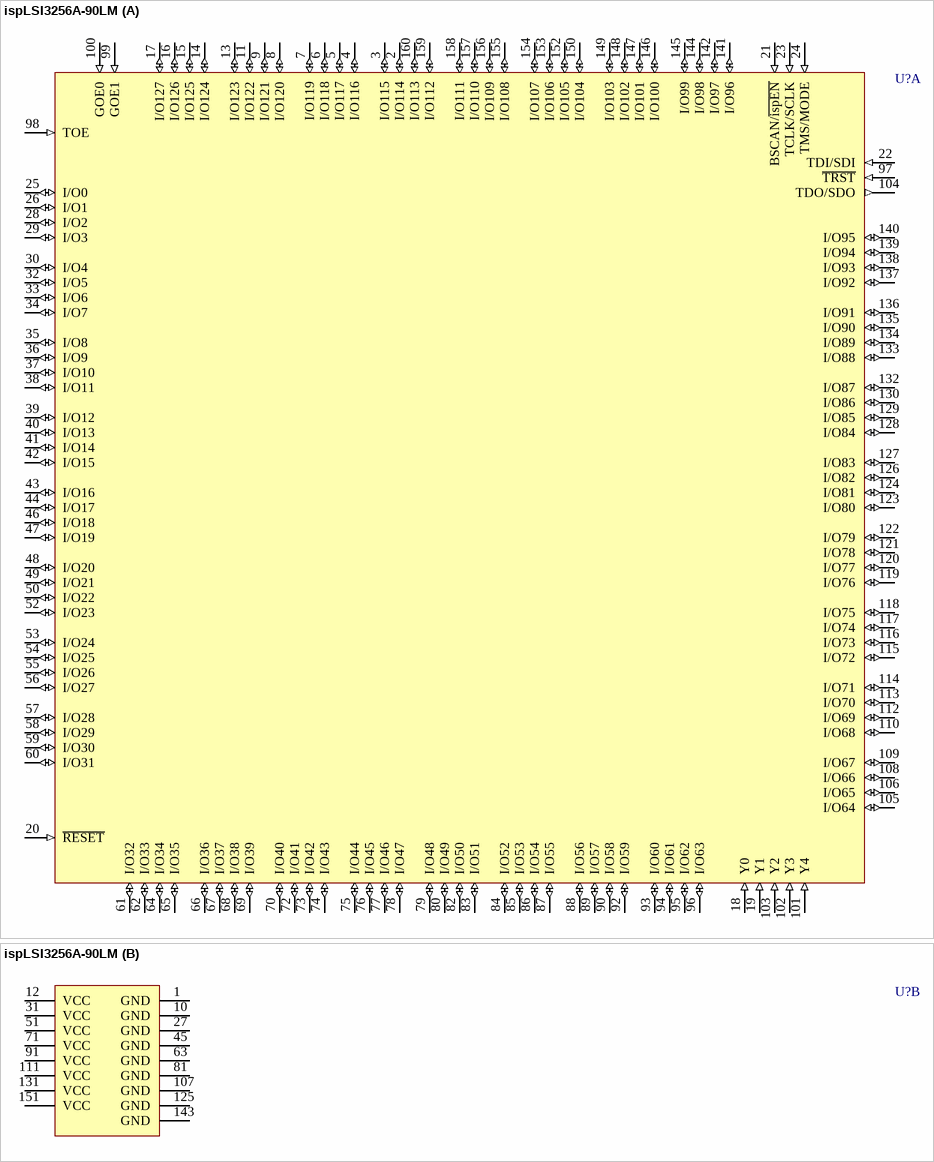
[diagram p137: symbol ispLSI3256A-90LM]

## ispLSI3256A-90LM
designator U?
In-System Programmable High-Density PLD; Note: Pins 21, 22, 23, 24 and 104 have dual function capability.
footprint MQFP160_N (QFP, 160-Leads, Body 27.7 x 27.7mm, Pitch 0.65mm, IPC Medium Density)
footprint MQFP160_L (QFP, 160-Leads, Body 27.7 x 27.7mm, Pitch 0.65mm, IPC High Density)
footprint MQFP160_M (QFP, 160-Leads, Body 27.7 x 27.7mm, Pitch 0.65mm, IPC Low Density)
3D model 3256A-MQFP160 (160-Pin Quad Flat Pack 0.65 mm Pitch)
part A pins: 2 I/O114 (io), 3 I/O115 (io), 4 I/O116 (io), 5 I/O117 (io), 6 I/O118 (io), 7 I/O119 (io), 8 I/O120 (io), 9 I/O121 (io), 11 I/O122 (io), 13 I/O123 (io), 14 I/O124 (io), 15 I/O125 (io), 16 I/O126 (io), 17 I/O127 (io), 18 Y0 (in), 19 Y1 (in), 20 ~{RESET} (in), 21 BSCAN/~{ispEN} (in), 22 TDI/SDI (in), 23 TCLK/SCLK (in), 24 TMS/MODE (in), 25 I/O0 (io), 26 I/O1 (io), 28 I/O2 (io), 29 I/O3 (io), 30 I/O4 (io), 32 I/O5 (io), 33 I/O6 (io), 34 I/O7 (io), 35 I/O8 (io), 36 I/O9 (io), 37 I/O10 (io), 38 I/O11 (io), 39 I/O12 (io), 40 I/O13 (io), 41 I/O14 (io), 42 I/O15 (io), 43 I/O16 (io), 44 I/O17 (io), 46 I/O18 (io), 47 I/O19 (io), 48 I/O20 (io), 49 I/O21 (io), 50 I/O22 (io), 52 I/O23 (io), 53 I/O24 (io), 54 I/O25 (io), 55 I/O26 (io), 56 I/O27 (io), 57 I/O28 (io), 58 I/O29 (io), 59 I/O30 (io), 60 I/O31 (io), 61 I/O32 (io), 62 I/O33 (io), 64 I/O34 (io), 65 I/O35 (io), 66 I/O36 (io), 67 I/O37 (io), 68 I/O38 (io), 69 I/O39 (io), 70 I/O40 (io), 72 I/O41 (io), 73 I/O42 (io), 74 I/O43 (io), 75 I/O44 (io), 76 I/O45 (io), 77 I/O46 (io), 78 I/O47 (io), 79 I/O48 (io), 80 I/O49 (io), 82 I/O50 (io), 83 I/O51 (io), 84 I/O52 (io), 85 I/O53 (io), 86 I/O54 (io), 87 I/O55 (io), 88 I/O56 (io), 89 I/O57 (io), 90 I/O58 (io), 92 I/O59 (io), 93 I/O60 (io), 94 I/O61 (io), 95 I/O62 (io), 96 I/O63 (io), 97 ~{TRST} (in), 98 TOE (in), 99 GOE1 (in), 100 GOE0 (in), 101 Y4 (in), 102 Y3 (in), 103 Y2 (in), 104 TDO/SDO (out), 105 I/O64 (io), 106 I/O65 (io), 108 I/O66 (io), 109 I/O67 (io), 110 I/O68 (io), 112 I/O69 (io), 113 I/O70 (io), 114 I/O71 (io), 115 I/O72 (io), 116 I/O73 (io), 117 I/O74 (io), 118 I/O75 (io), 119 I/O76 (io), 120 I/O77 (io), 121 I/O78 (io), 122 I/O79 (io), 123 I/O80 (io), 124 I/O81 (io), 126 I/O82 (io), 127 I/O83 (io), 128 I/O84 (io), 129 I/O85 (io), 130 I/O86 (io), 132 I/O87 (io), 133 I/O88 (io), 134 I/O89 (io), 135 I/O90 (io), 136 I/O91 (io), 137 I/O92 (io), 138 I/O93 (io), 139 I/O94 (io), 140 I/O95 (io), 141 I/O96 (io), 142 I/O97 (io), 144 I/O98 (io), 145 I/O99 (io), 146 I/O100 (io), 147 I/O101 (io), 148 I/O102 (io), 149 I/O103 (io), 150 I/O104 (io), 152 I/O105 (io), 153 I/O106 (io), 154 I/O107 (io), 155 I/O108 (io), 156 I/O109 (io), 157 I/O110 (io), 158 I/O111 (io), 159 I/O112 (io), 160 I/O113 (io)
part B pins: 1 GND (power), 10 GND (power), 12 VCC (power), 27 GND (power), 31 VCC (power), 45 GND (power), 51 VCC (power), 63 GND (power), 71 VCC (power), 81 GND (power), 91 VCC (power), 107 GND (power), 111 VCC (power), 125 GND (power), 131 VCC (power), 143 GND (power), 151 VCC (power)

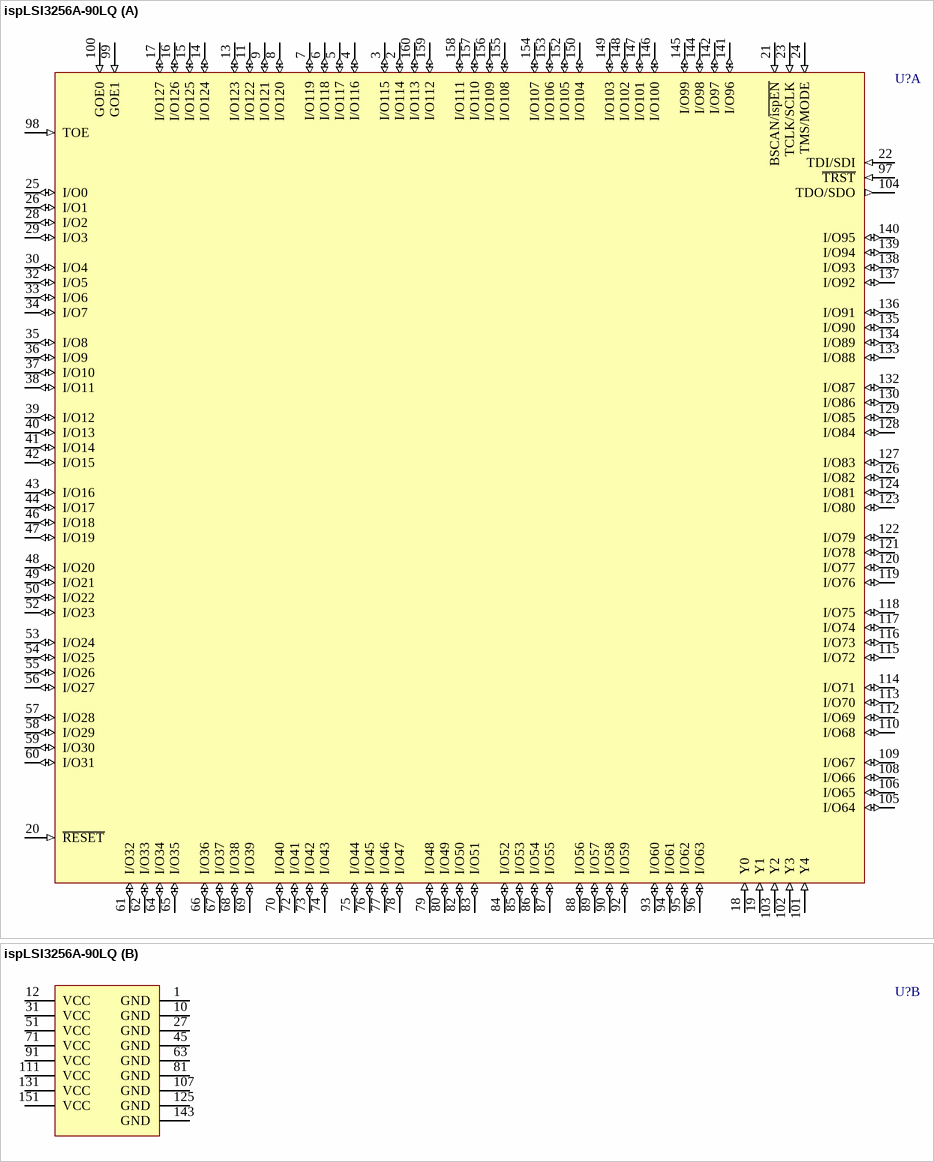
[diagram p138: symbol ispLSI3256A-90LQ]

## ispLSI3256A-90LQ
designator U?
In-System Programmable High-Density PLD; Note: Pins 21, 22, 23, 24 and 104 have dual function capability.
footprint PQFP160_N (QFP, 160-Leads, Body 28 x 28mm, Pitch 0.65mm, IPC Medium Density)
footprint PQFP160_L (QFP, 160-Leads, Body 28 x 28mm, Pitch 0.65mm, IPC High Density)
footprint PQFP160_M (QFP, 160-Leads, Body 28 x 28mm, Pitch 0.65mm, IPC Low Density)
3D model 3256A-PQFP160 (160-Pin Quad Flat Pack 0.65 mm Pitch)
part A pins: 2 I/O114 (io), 3 I/O115 (io), 4 I/O116 (io), 5 I/O117 (io), 6 I/O118 (io), 7 I/O119 (io), 8 I/O120 (io), 9 I/O121 (io), 11 I/O122 (io), 13 I/O123 (io), 14 I/O124 (io), 15 I/O125 (io), 16 I/O126 (io), 17 I/O127 (io), 18 Y0 (in), 19 Y1 (in), 20 ~{RESET} (in), 21 BSCAN/~{ispEN} (in), 22 TDI/SDI (in), 23 TCLK/SCLK (in), 24 TMS/MODE (in), 25 I/O0 (io), 26 I/O1 (io), 28 I/O2 (io), 29 I/O3 (io), 30 I/O4 (io), 32 I/O5 (io), 33 I/O6 (io), 34 I/O7 (io), 35 I/O8 (io), 36 I/O9 (io), 37 I/O10 (io), 38 I/O11 (io), 39 I/O12 (io), 40 I/O13 (io), 41 I/O14 (io), 42 I/O15 (io), 43 I/O16 (io), 44 I/O17 (io), 46 I/O18 (io), 47 I/O19 (io), 48 I/O20 (io), 49 I/O21 (io), 50 I/O22 (io), 52 I/O23 (io), 53 I/O24 (io), 54 I/O25 (io), 55 I/O26 (io), 56 I/O27 (io), 57 I/O28 (io), 58 I/O29 (io), 59 I/O30 (io), 60 I/O31 (io), 61 I/O32 (io), 62 I/O33 (io), 64 I/O34 (io), 65 I/O35 (io), 66 I/O36 (io), 67 I/O37 (io), 68 I/O38 (io), 69 I/O39 (io), 70 I/O40 (io), 72 I/O41 (io), 73 I/O42 (io), 74 I/O43 (io), 75 I/O44 (io), 76 I/O45 (io), 77 I/O46 (io), 78 I/O47 (io), 79 I/O48 (io), 80 I/O49 (io), 82 I/O50 (io), 83 I/O51 (io), 84 I/O52 (io), 85 I/O53 (io), 86 I/O54 (io), 87 I/O55 (io), 88 I/O56 (io), 89 I/O57 (io), 90 I/O58 (io), 92 I/O59 (io), 93 I/O60 (io), 94 I/O61 (io), 95 I/O62 (io), 96 I/O63 (io), 97 ~{TRST} (in), 98 TOE (in), 99 GOE1 (in), 100 GOE0 (in), 101 Y4 (in), 102 Y3 (in), 103 Y2 (in), 104 TDO/SDO (out), 105 I/O64 (io), 106 I/O65 (io), 108 I/O66 (io), 109 I/O67 (io), 110 I/O68 (io), 112 I/O69 (io), 113 I/O70 (io), 114 I/O71 (io), 115 I/O72 (io), 116 I/O73 (io), 117 I/O74 (io), 118 I/O75 (io), 119 I/O76 (io), 120 I/O77 (io), 121 I/O78 (io), 122 I/O79 (io), 123 I/O80 (io), 124 I/O81 (io), 126 I/O82 (io), 127 I/O83 (io), 128 I/O84 (io), 129 I/O85 (io), 130 I/O86 (io), 132 I/O87 (io), 133 I/O88 (io), 134 I/O89 (io), 135 I/O90 (io), 136 I/O91 (io), 137 I/O92 (io), 138 I/O93 (io), 139 I/O94 (io), 140 I/O95 (io), 141 I/O96 (io), 142 I/O97 (io), 144 I/O98 (io), 145 I/O99 (io), 146 I/O100 (io), 147 I/O101 (io), 148 I/O102 (io), 149 I/O103 (io), 150 I/O104 (io), 152 I/O105 (io), 153 I/O106 (io), 154 I/O107 (io), 155 I/O108 (io), 156 I/O109 (io), 157 I/O110 (io), 158 I/O111 (io), 159 I/O112 (io), 160 I/O113 (io)
part B pins: 1 GND (power), 10 GND (power), 12 VCC (power), 27 GND (power), 31 VCC (power), 45 GND (power), 51 VCC (power), 63 GND (power), 71 VCC (power), 81 GND (power), 91 VCC (power), 107 GND (power), 111 VCC (power), 125 GND (power), 131 VCC (power), 143 GND (power), 151 VCC (power)

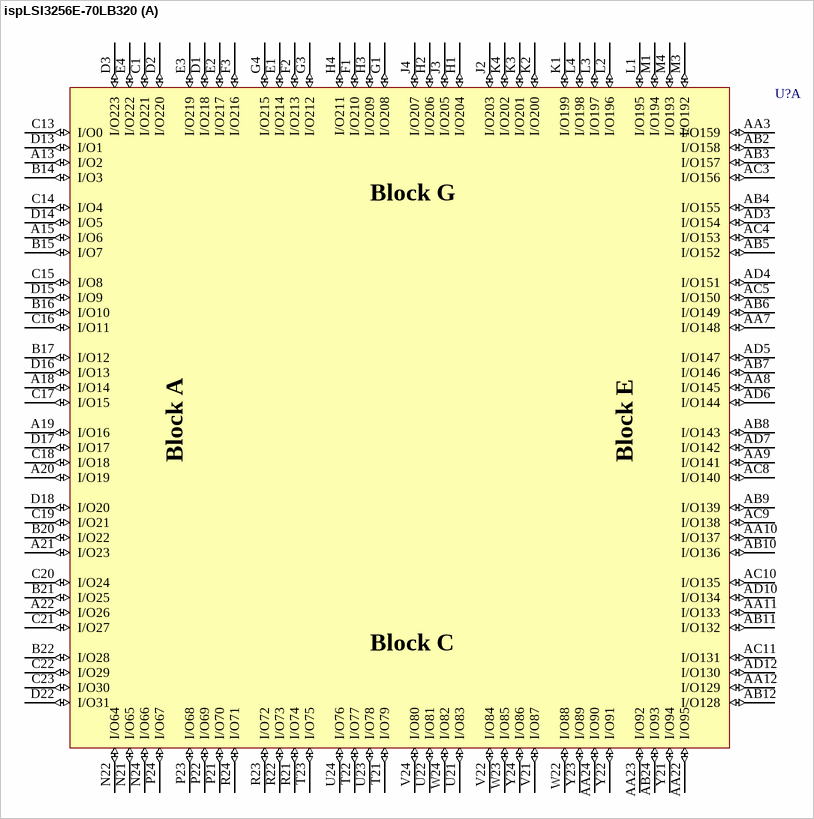
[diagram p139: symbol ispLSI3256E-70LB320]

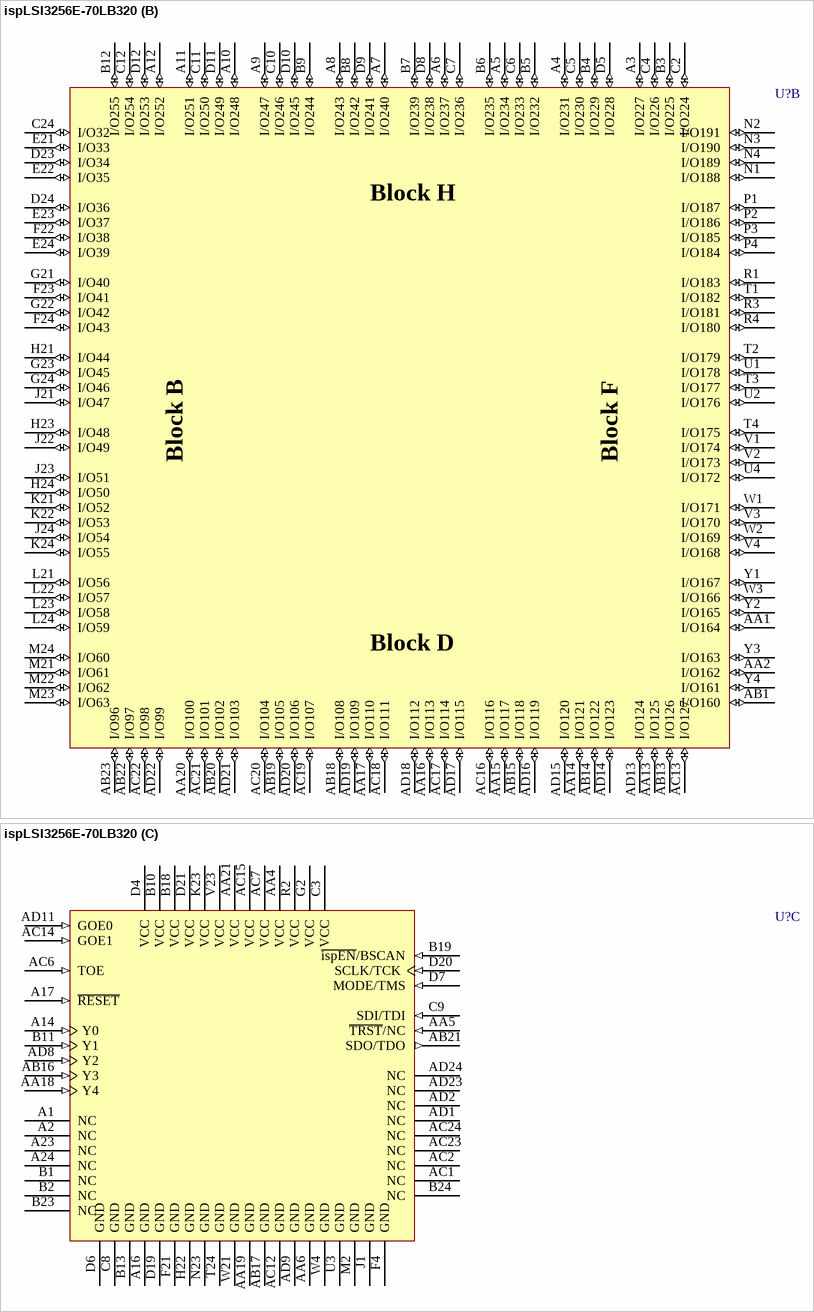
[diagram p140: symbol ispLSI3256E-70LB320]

## ispLSI3256E-70LB320
designator U?
In-System Programmable High-Density PLD
footprint SBGA320 (BGA, 320-Leads, Body 31x31mm, Pitch 1.27mm)
3D model 3256E-SBGA320 (320-Ball Super Ball Grid Array (SBGA320))
part A pins: A13 I/O2 (io), A15 I/O6 (io), A18 I/O14 (io), A19 I/O16 (io), A20 I/O19 (io), A21 I/O23 (io), A22 I/O26 (io), AA3 I/O159 (io), AA7 I/O148 (io), AA8 I/O145 (io), AA9 I/O141 (io), AA10 I/O137 (io), AA11 I/O133 (io), AA12 I/O129 (io), AA22 I/O95 (io), AA23 I/O92 (io), AA24 I/O90 (io), AB2 I/O158 (io), AB3 I/O157 (io), AB4 I/O155 (io), AB5 I/O152 (io), AB6 I/O149 (io), AB7 I/O146 (io), AB8 I/O143 (io), AB9 I/O139 (io), AB10 I/O136 (io), AB11 I/O132 (io), AB12 I/O128 (io), AB24 I/O93 (io), AC3 I/O156 (io), AC4 I/O153 (io), AC5 I/O150 (io), AC8 I/O140 (io), AC9 I/O138 (io), AC10 I/O135 (io), AC11 I/O131 (io), AD3 I/O154 (io), AD4 I/O151 (io), AD5 I/O147 (io), AD6 I/O144 (io), AD7 I/O142 (io), AD10 I/O134 (io), AD12 I/O130 (io), B14 I/O3 (io), B15 I/O7 (io), B16 I/O10 (io), B17 I/O12 (io), B20 I/O22 (io), B21 I/O25 (io), B22 I/O28 (io), C1 I/O221 (io), C13 I/O0 (io), C14 I/O4 (io), C15 I/O8 (io), C16 I/O11 (io), C17 I/O15 (io), C18 I/O18 (io), C19 I/O21 (io), C20 I/O24 (io), C21 I/O27 (io), C22 I/O29 (io), C23 I/O30 (io), D1 I/O218 (io), D2 I/O220 (io), D3 I/O223 (io), D13 I/O1 (io), D14 I/O5 (io), D15 I/O9 (io), D16 I/O13 (io), D17 I/O17 (io), D18 I/O20 (io), D22 I/O31 (io), E1 I/O214 (io), E2 I/O217 (io), E3 I/O219 (io), E4 I/O222 (io), F1 I/O210 (io), F2 I/O213 (io), F3 I/O216 (io), G1 I/O208 (io), G3 I/O212 (io), G4 I/O215 (io), H1 I/O204 (io), H2 I/O206 (io), H3 I/O209 (io), H4 I/O211 (io), J2 I/O203 (io), J3 I/O205 (io), J4 I/O207 (io), K1 I/O199 (io), K2 I/O200 (io), K3 I/O201 (io), K4 I/O202 (io), L1 I/O195 (io), L2 I/O196 (io), L3 I/O197 (io), L4 I/O198 (io), M1 I/O194 (io), M3 I/O192 (io), M4 I/O193 (io), N21 I/O65 (io), N22 I/O64 (io), N24 I/O66 (io), P21 I/O70 (io), P22 I/O69 (io), P23 I/O68 (io), P24 I/O67 (io), R21 I/O74 (io), R22 I/O73 (io), R23 I/O72 (io), R24 I/O71 (io), T21 I/O79 (io), T22 I/O77 (io), T23 I/O75 (io), U21 I/O83 (io), U22 I/O81 (io), U23 I/O78 (io), U24 I/O76 (io), V21 I/O87 (io), V22 I/O84 (io), V24 I/O80 (io), W22 I/O88 (io), W23 I/O85 (io), W24 I/O82 (io), Y21 I/O94 (io), Y22 I/O91 (io), Y23 I/O89 (io), Y24 I/O86 (io)
part B pins: A3 I/O227 (io), A4 I/O231 (io), A5 I/O234 (io), A6 I/O237 (io), A7 I/O240 (io), A8 I/O243 (io), A9 I/O247 (io), A10 I/O248 (io), A11 I/O251 (io), A12 I/O252 (io), AA1 I/O164 (io), AA2 I/O162 (io), AA13 I/O125 (io), AA14 I/O121 (io), AA15 I/O117 (io), AA16 I/O113 (io), AA17 I/O110 (io), AA20 I/O100 (io), AB1 I/O160 (io), AB13 I/O126 (io), AB14 I/O122 (io), AB15 I/O118 (io), AB18 I/O108 (io), AB19 I/O105 (io), AB20 I/O102 (io), AB22 I/O97 (io), AB23 I/O96 (io), AC13 I/O127 (io), AC16 I/O116 (io), AC17 I/O114 (io), AC18 I/O111 (io), AC19 I/O107 (io), AC20 I/O104 (io), AC21 I/O101 (io), AC22 I/O98 (io), AD13 I/O124 (io), AD14 I/O123 (io), AD15 I/O120 (io), AD16 I/O119 (io), AD17 I/O115 (io), AD18 I/O112 (io), AD19 I/O109 (io), AD20 I/O106 (io), AD21 I/O103 (io), AD22 I/O99 (io), B3 I/O225 (io), B4 I/O229 (io), B5 I/O232 (io), B6 I/O235 (io), B7 I/O239 (io), B8 I/O242 (io), B9 I/O244 (io), B12 I/O255 (io), C2 I/O224 (io), C4 I/O226 (io), C5 I/O230 (io), C6 I/O233 (io), C7 I/O236 (io), C10 I/O246 (io), C11 I/O250 (io), C12 I/O254 (io), C24 I/O32 (io), D5 I/O228 (io), D8 I/O238 (io), D9 I/O241 (io), D10 I/O245 (io), D11 I/O249 (io), D12 I/O253 (io), D23 I/O34 (io), D24 I/O36 (io), E21 I/O33 (io), E22 I/O35 (io), E23 I/O37 (io), E24 I/O39 (io), F22 I/O38 (io), F23 I/O41 (io), F24 I/O43 (io), G21 I/O40 (io), G22 I/O42 (io), G23 I/O45 (io), G24 I/O46 (io), H21 I/O44 (io), H23 I/O48 (io), H24 I/O50 (io), J21 I/O47 (io), J22 I/O49 (io), J23 I/O51 (io), J24 I/O54 (io), K21 I/O52 (io), K22 I/O53 (io), K24 I/O55 (io), L21 I/O56 (io), L22 I/O57 (io), L23 I/O58 (io), L24 I/O59 (io), M21 I/O61 (io), M22 I/O62 (io), M23 I/O63 (io), M24 I/O60 (io), N1 I/O188 (io), N2 I/O191 (io), N3 I/O190 (io), N4 I/O189 (io), P1 I/O187 (io), P2 I/O186 (io), P3 I/O185 (io), P4 I/O184 (io), R1 I/O183 (io), R3 I/O181 (io), R4 I/O180 (io), T1 I/O182 (io), T2 I/O179 (io), T3 I/O177 (io), T4 I/O175 (io), U1 I/O178 (io), U2 I/O176 (io), U4 I/O172 (io), V1 I/O174 (io), V2 I/O173 (io), V3 I/O170 (io), V4 I/O168 (io), W1 I/O171 (io), W2 I/O169 (io), W3 I/O166 (io), Y1 I/O167 (io), Y2 I/O165 (io), Y3 I/O163 (io), Y4 I/O161 (io)
part C pins: A1 NC, A2 NC, A14 Y0 (in), A16 GND (power), A17 ~{RESET} (in), A23 NC, A24 NC, AA4 VCC (power), AA5 ~{TRST}/NC (in), AA6 GND (power), AA18 Y4 (in), AA19 GND (power), AA21 VCC (power), AB16 Y3 (in), AB17 GND (power), AB21 SDO/TDO (out), AC1 NC, AC2 NC, AC6 TOE (in), AC7 VCC (power), AC12 GND (power), AC14 GOE1 (in), AC15 VCC (power), AC23 NC, AC24 NC, AD1 NC, AD2 NC, AD8 Y2 (in), AD9 GND (power), AD11 GOE0 (in), AD23 NC, AD24 NC, B1 NC, B2 NC, B10 VCC (power), B11 Y1 (in), B13 GND (power), B18 VCC (power), B19 ~{ispEN}/BSCAN (in), B23 NC, B24 NC, C3 VCC (power), C8 GND (power), C9 SDI/TDI (in), D4 VCC (power), D6 GND (power), D7 MODE/TMS (in), D19 GND (power), D20 SCLK/TCK (in), D21 VCC (power), F4 GND (power), F21 GND (power), G2 VCC (power), H22 GND (power), J1 GND (power), K23 VCC (power), M2 GND (power), N23 GND (power), R2 VCC (power), T24 GND (power), U3 GND (power), V23 VCC (power), W4 GND (power), W21 GND (power)

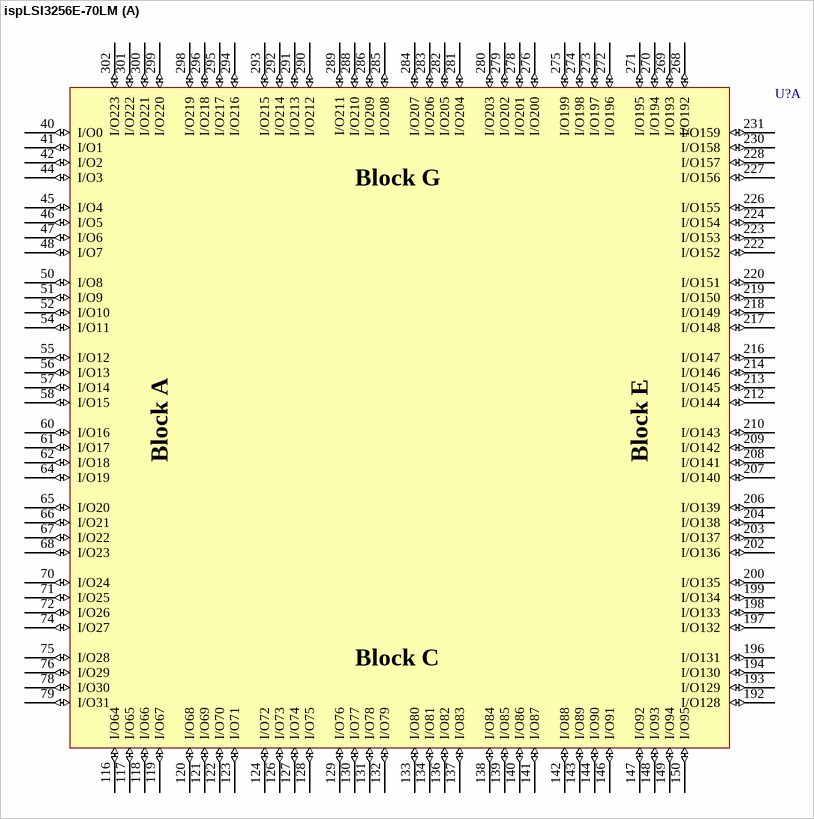
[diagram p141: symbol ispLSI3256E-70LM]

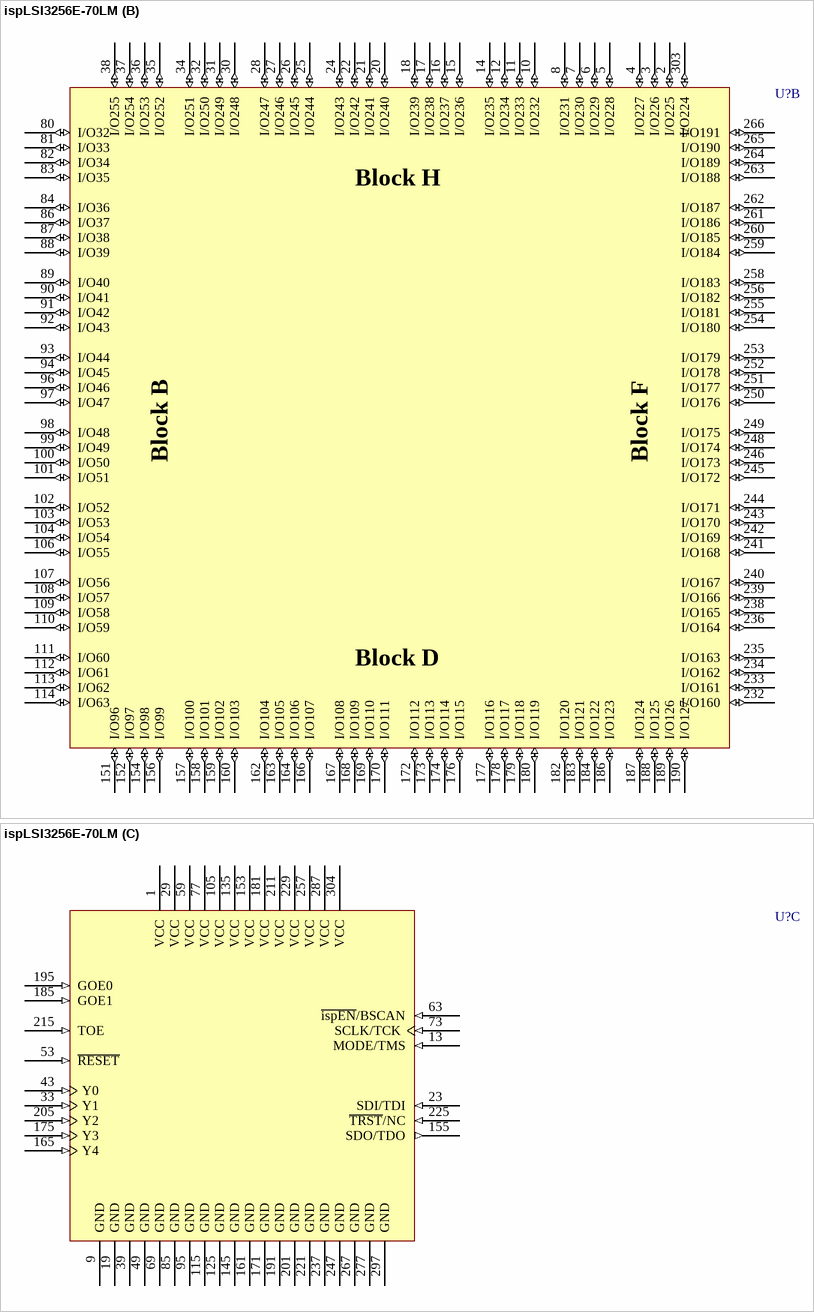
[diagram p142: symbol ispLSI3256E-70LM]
